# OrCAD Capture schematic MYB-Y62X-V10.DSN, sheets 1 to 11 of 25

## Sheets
1 PAGE16 - CAN: size C; title: MYB-Y62X-V01; rev: V1.0; note: RS485 & MCU_MCAN
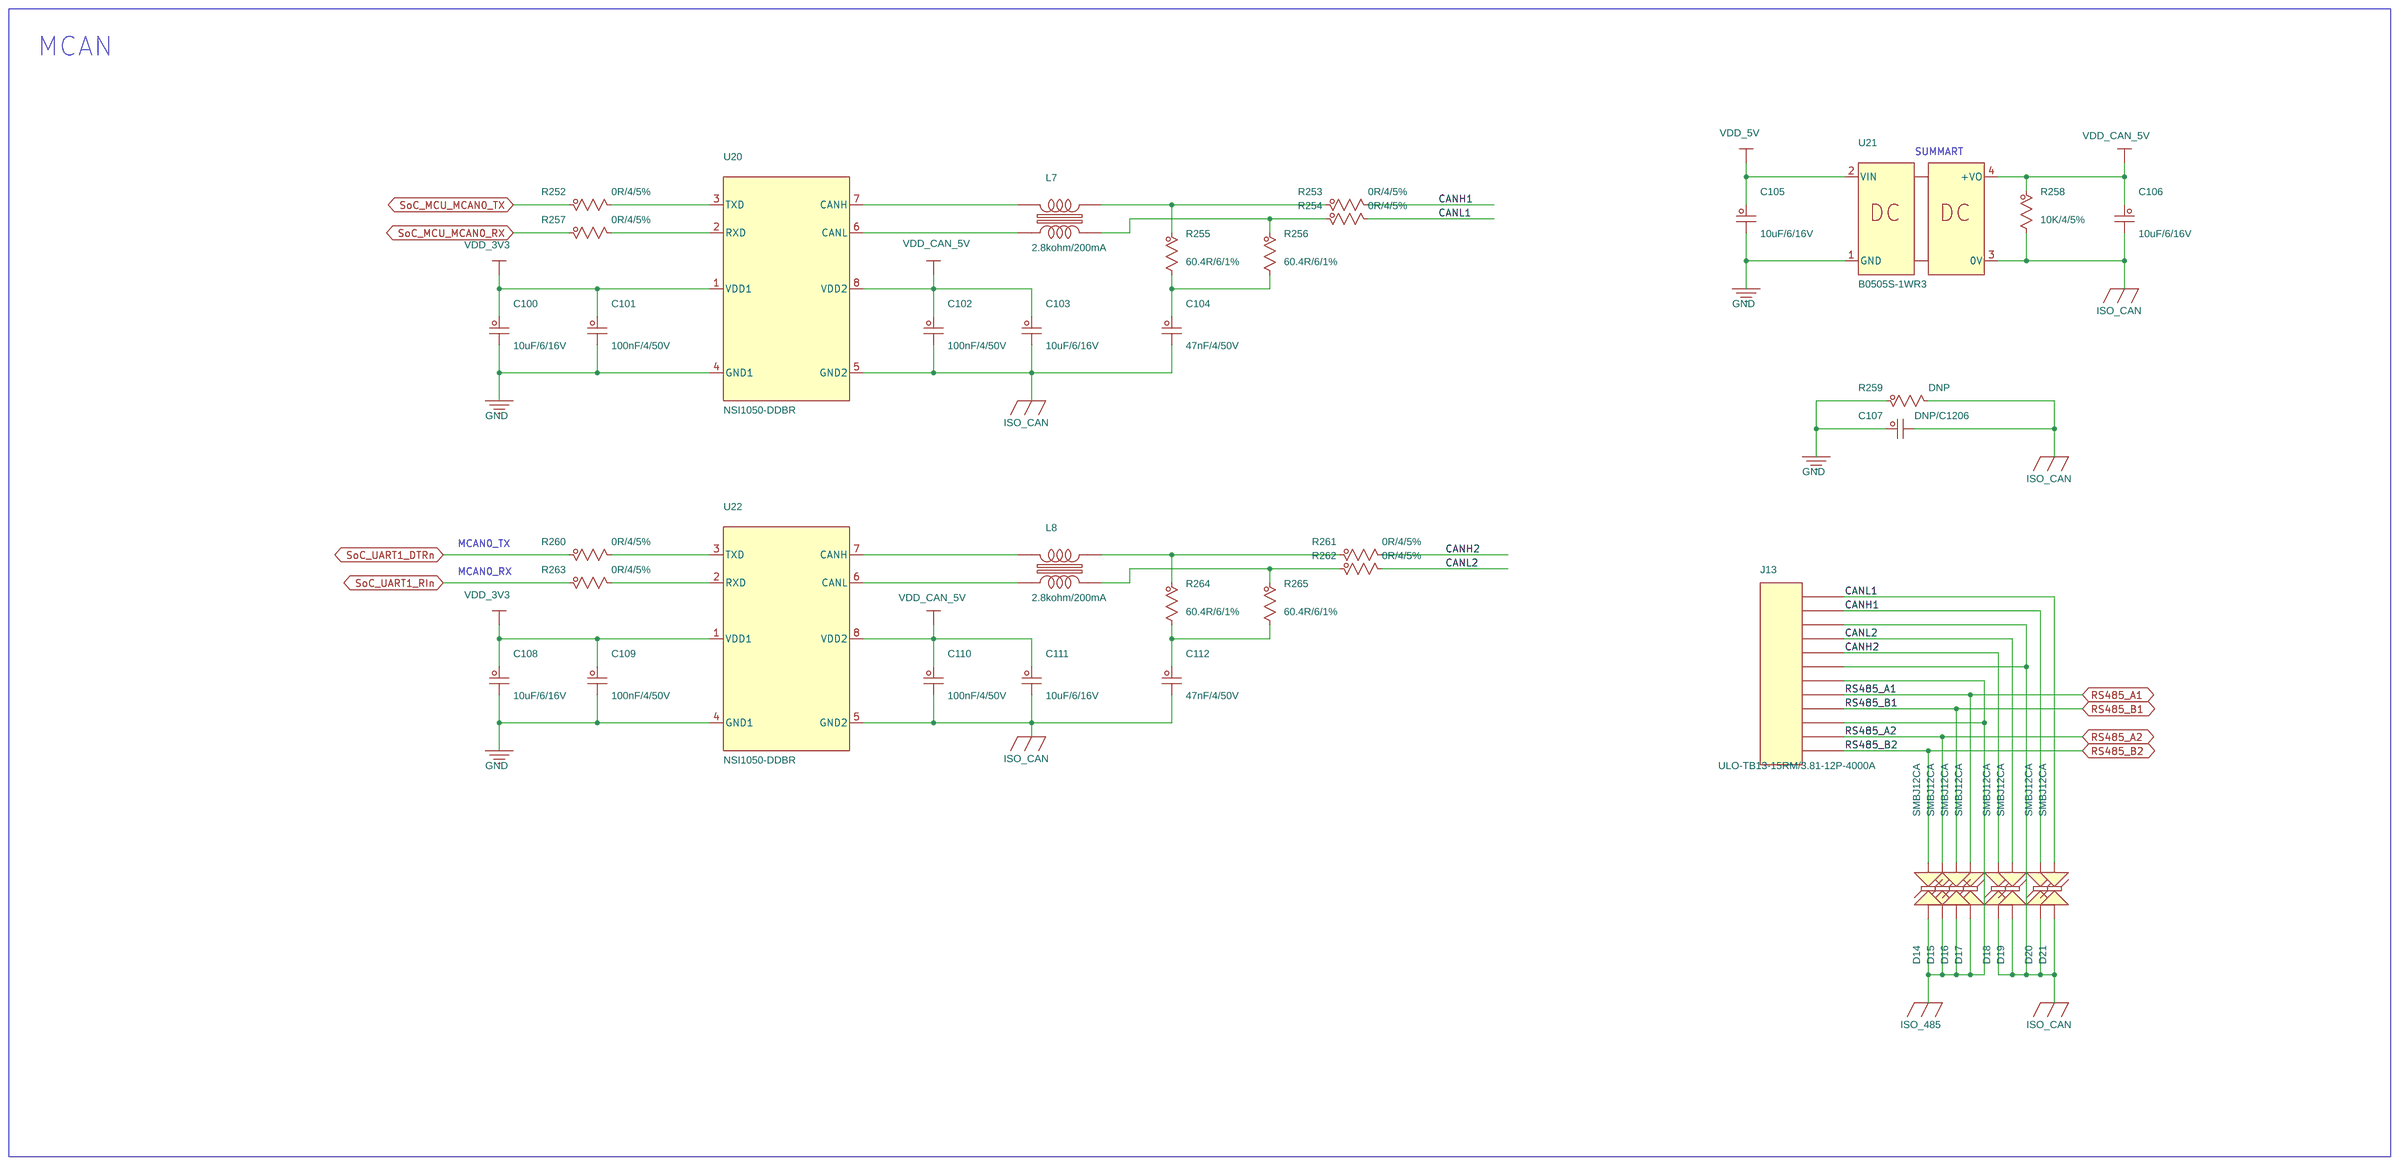
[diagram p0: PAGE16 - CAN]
2 PAGE15 - RS485: size C
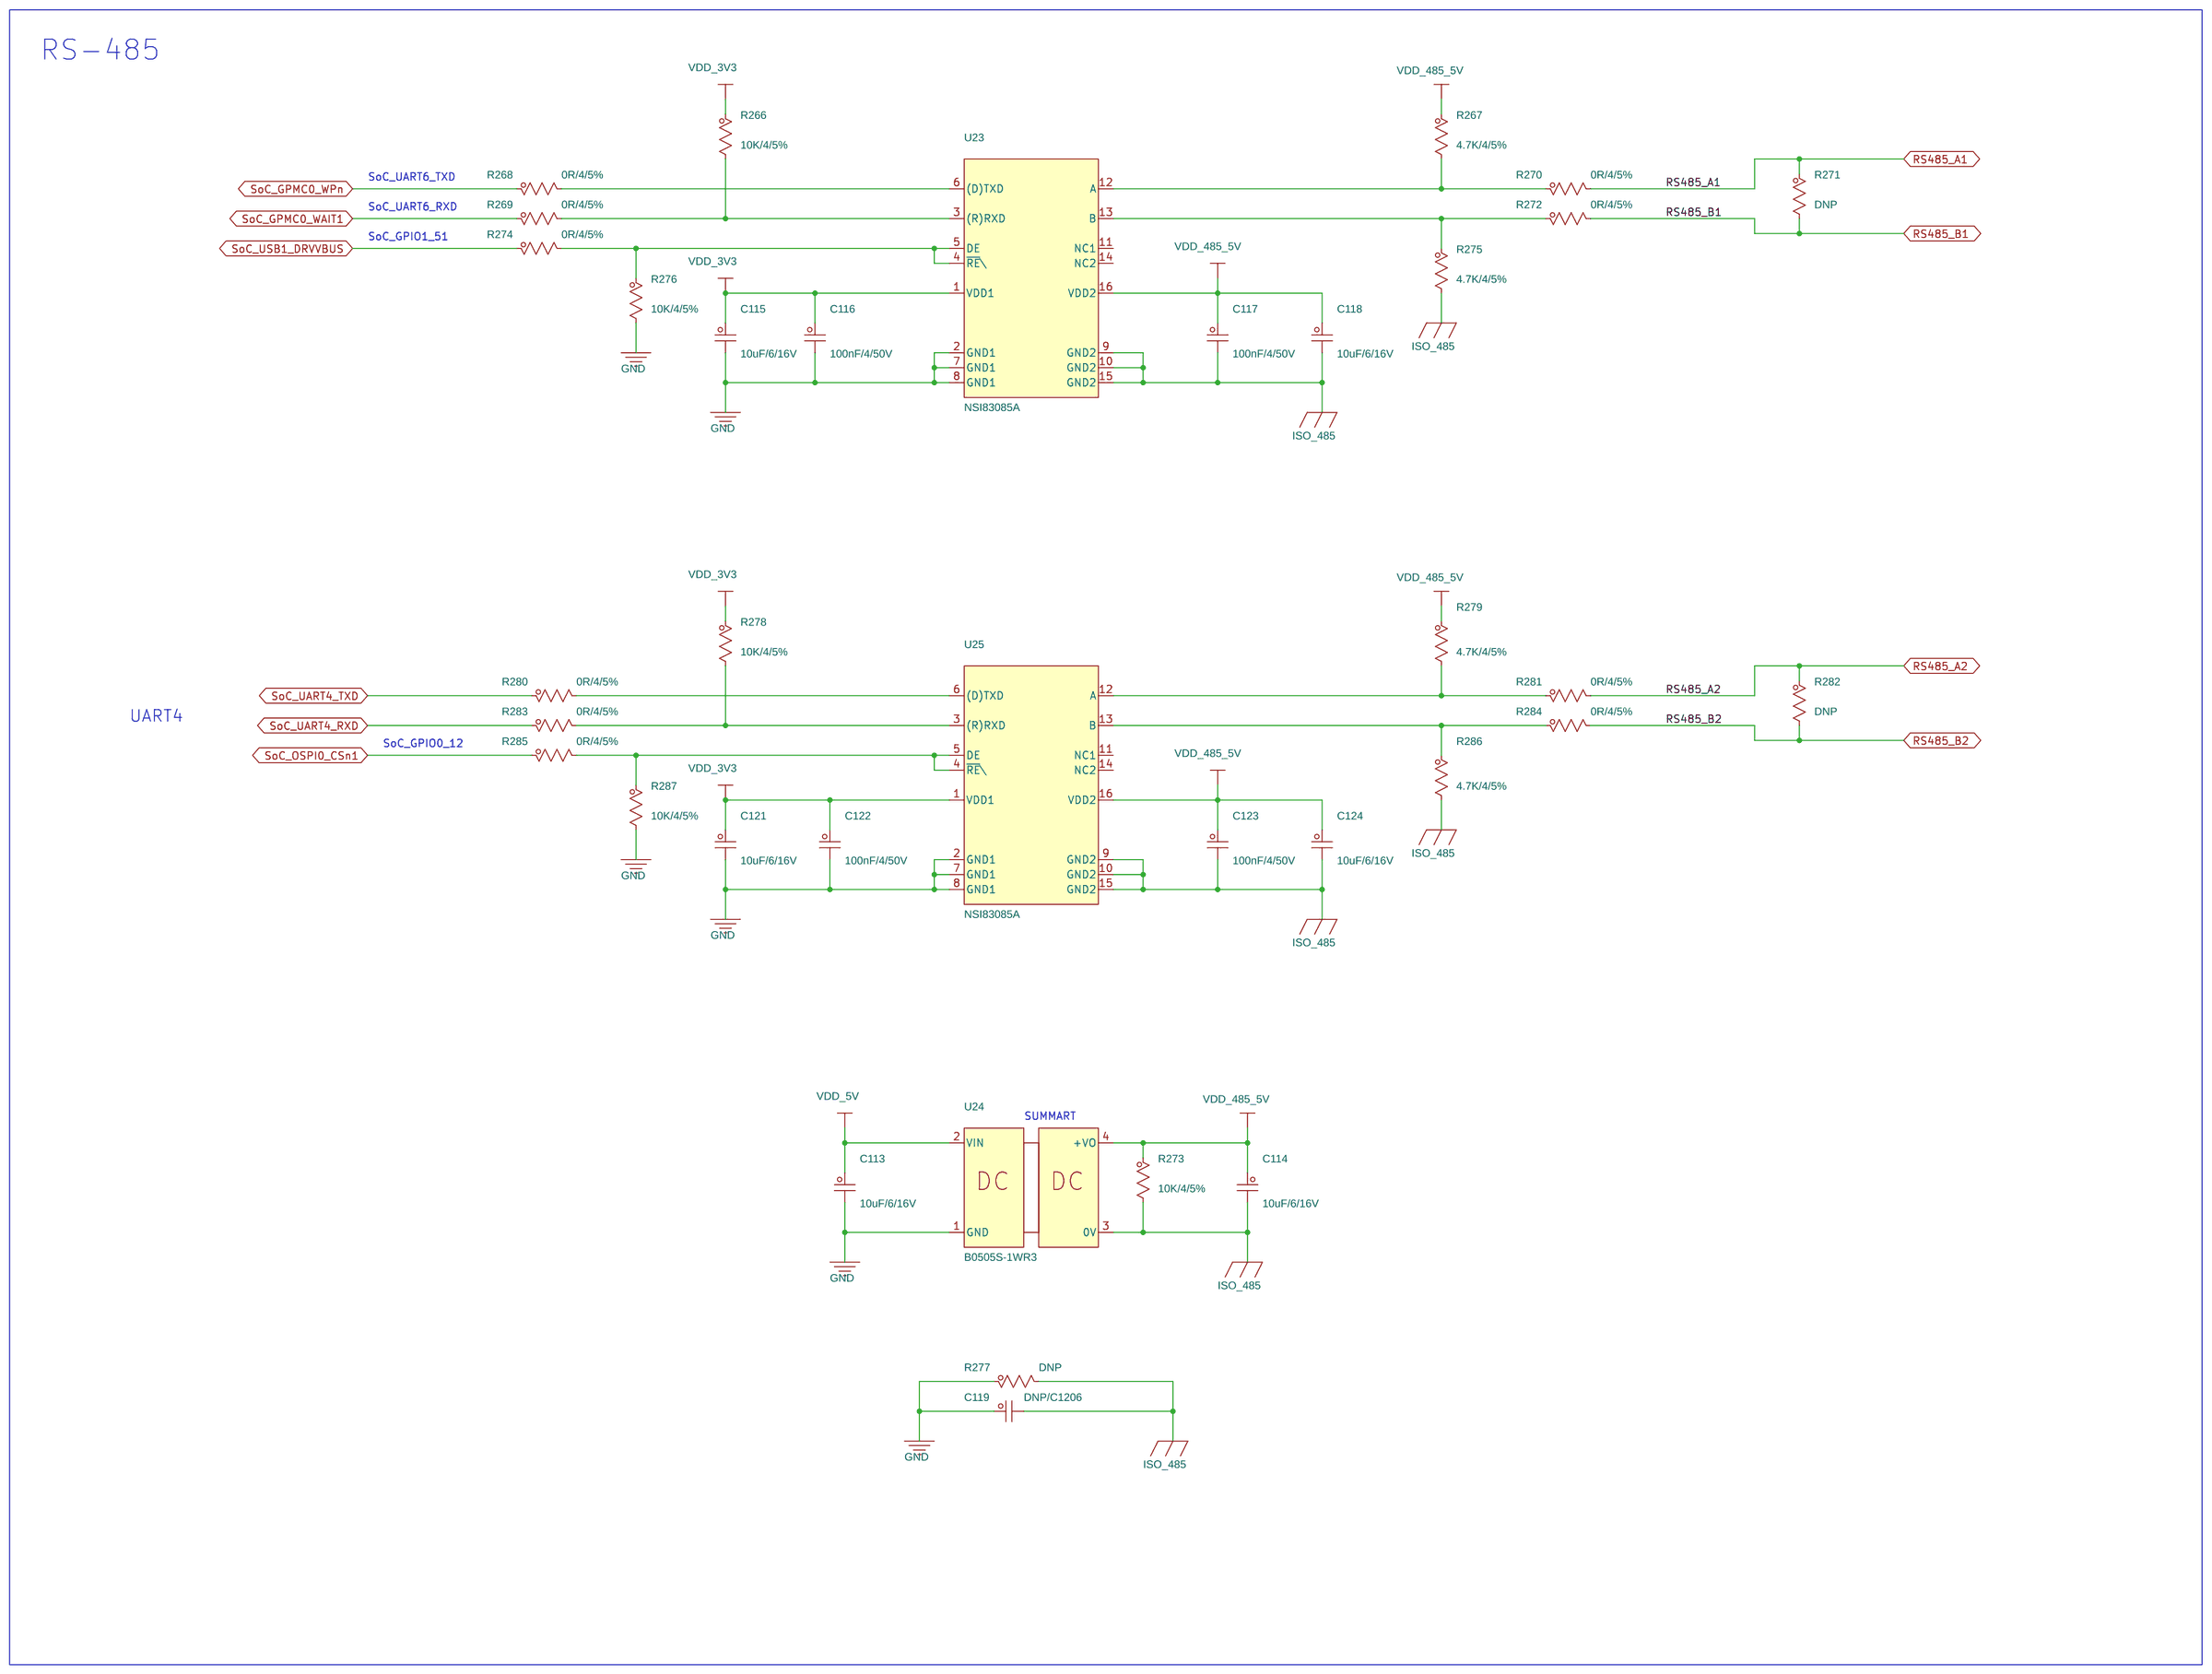
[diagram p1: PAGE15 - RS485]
3 PAGE01- REVISION HISTORY: note: REVISION HISTORY
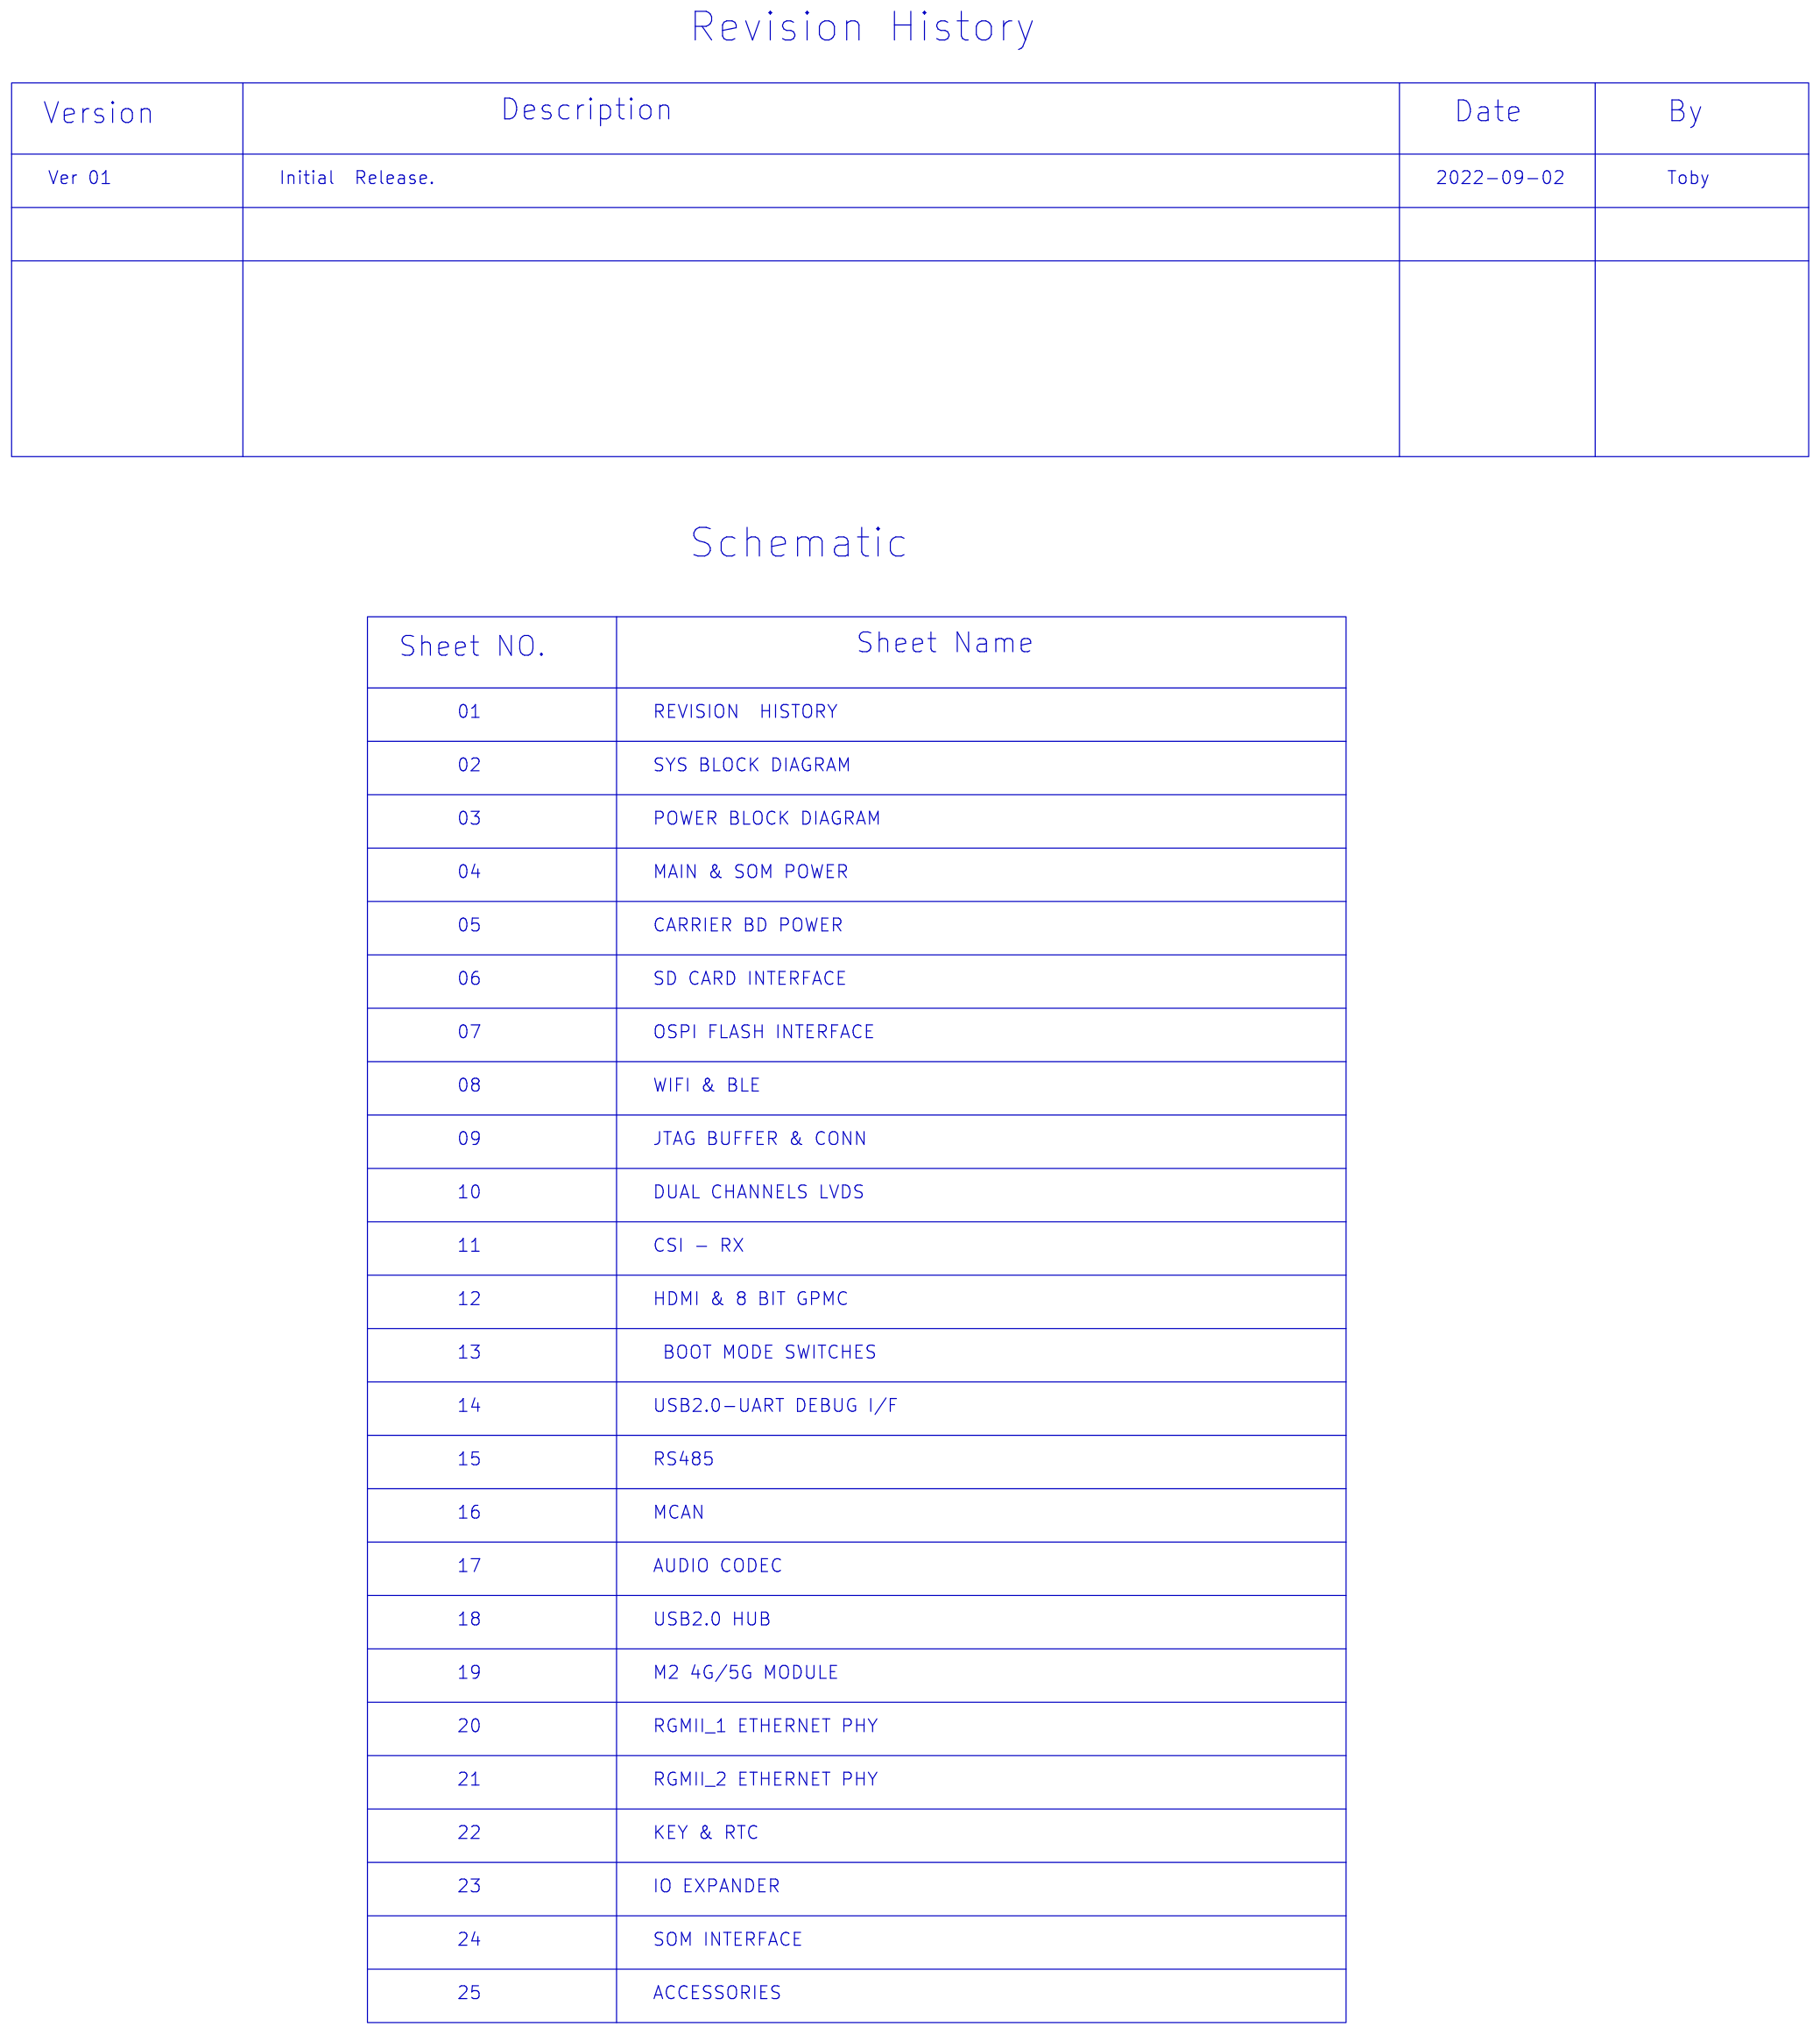
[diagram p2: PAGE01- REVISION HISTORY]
4 PAGE02 - SYS BLOCK DIAGRAM: note: SYS BLOCK DIAGRAM
5 PAGE03 - POWER BLOCK DIAGRAM: note: POWER BLOCK DIAGRAM
6 PAGE04 - MAIN & SOM POWER #: size B; note: MAIN & SOM POWER
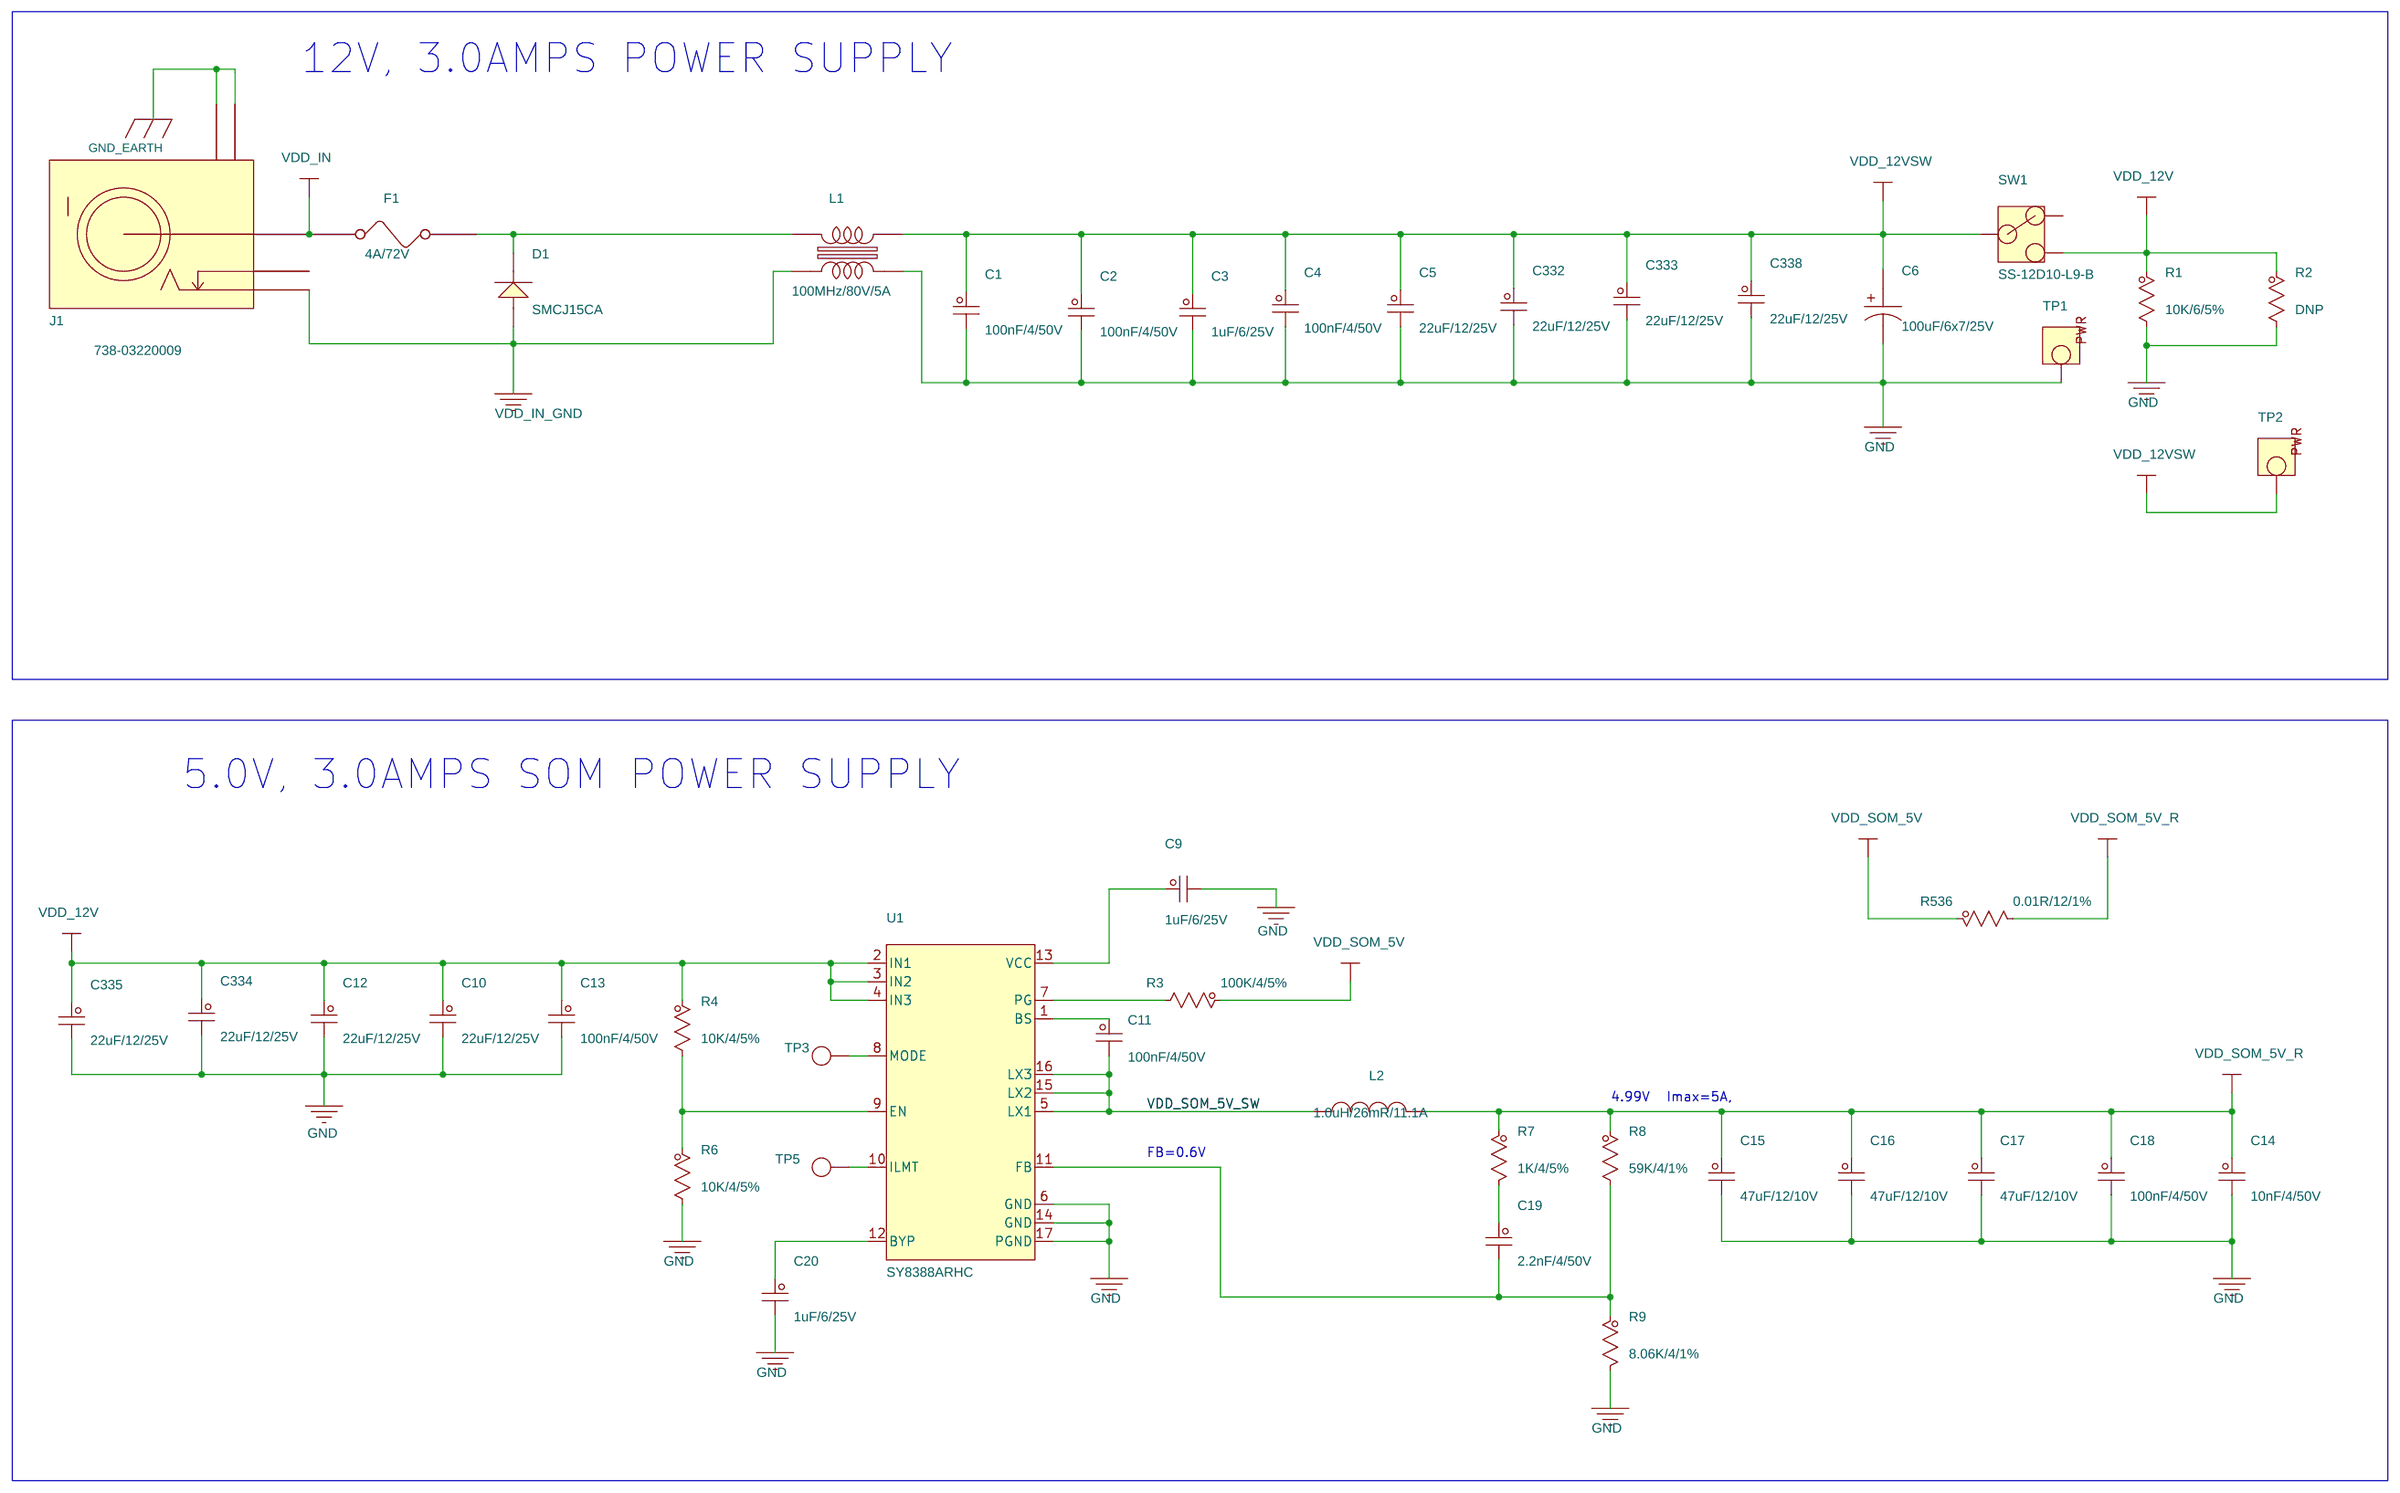
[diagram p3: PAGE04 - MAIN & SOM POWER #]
7 PAGE05 - CARRIER BD POWER #: size A3; note: CARRIER BD POWER
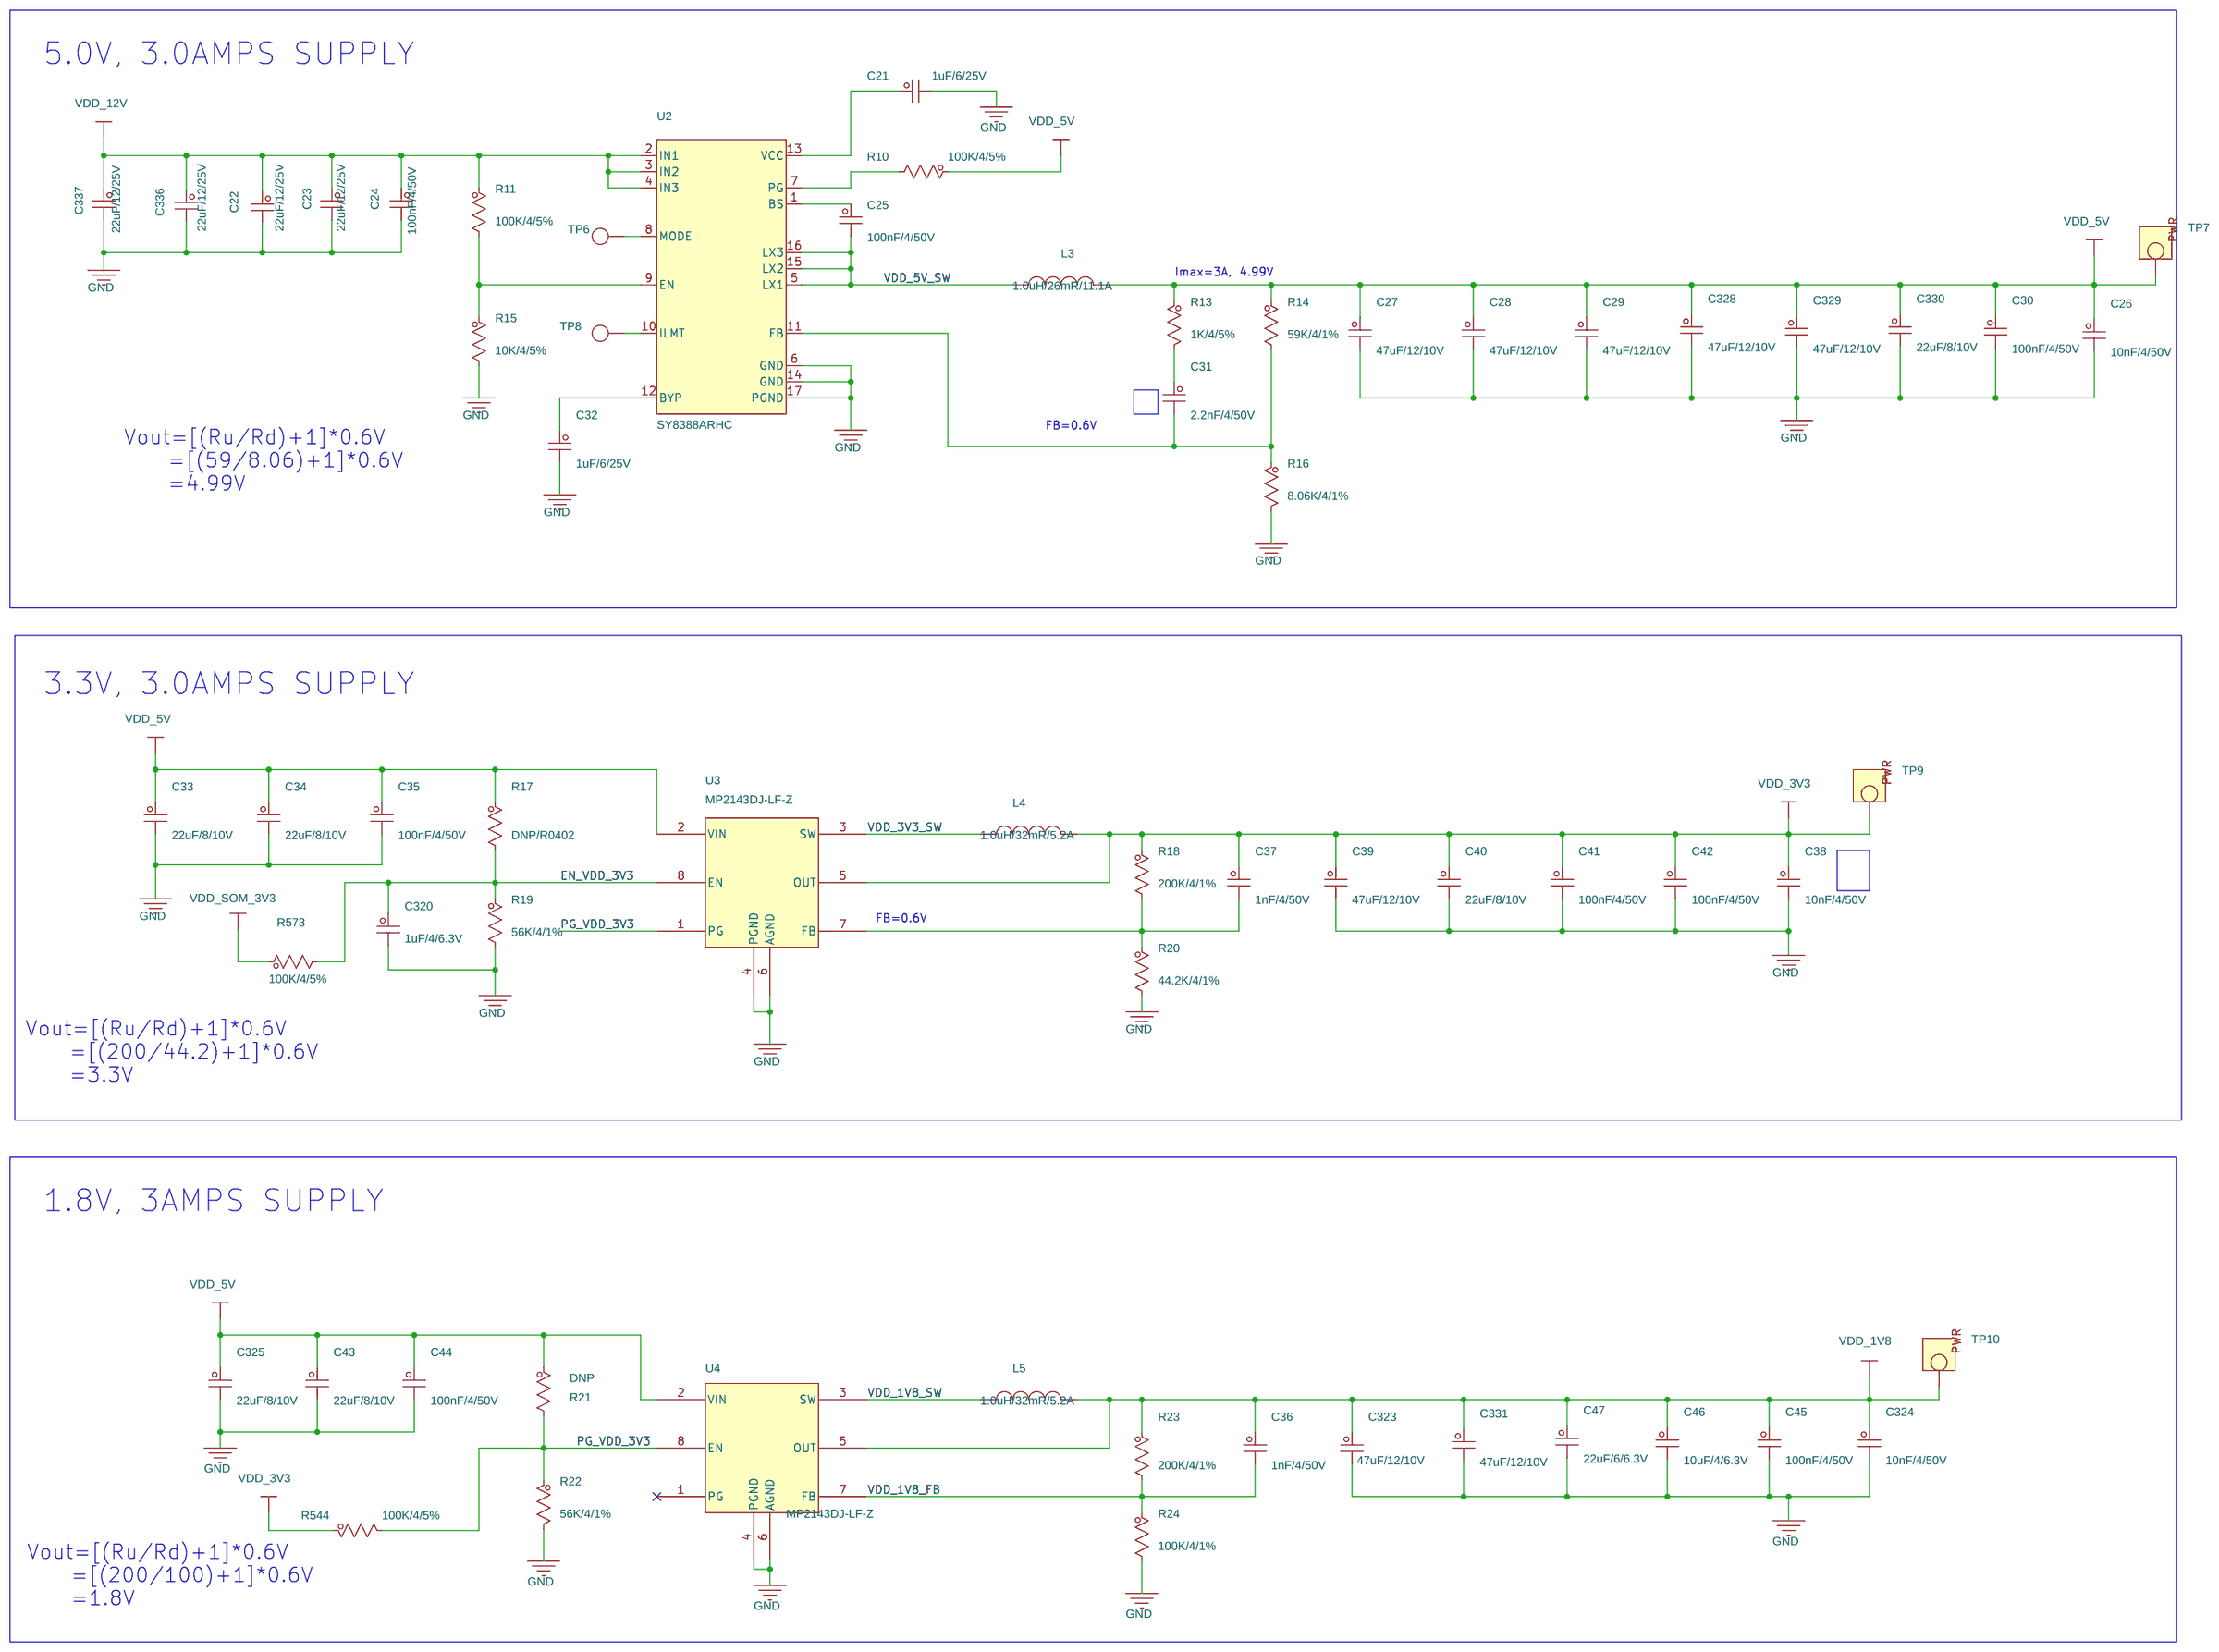
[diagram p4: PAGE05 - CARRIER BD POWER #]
8 PAGE06 - SD CARD INTERFACE #: size B; note: SD CARD INTERFACE
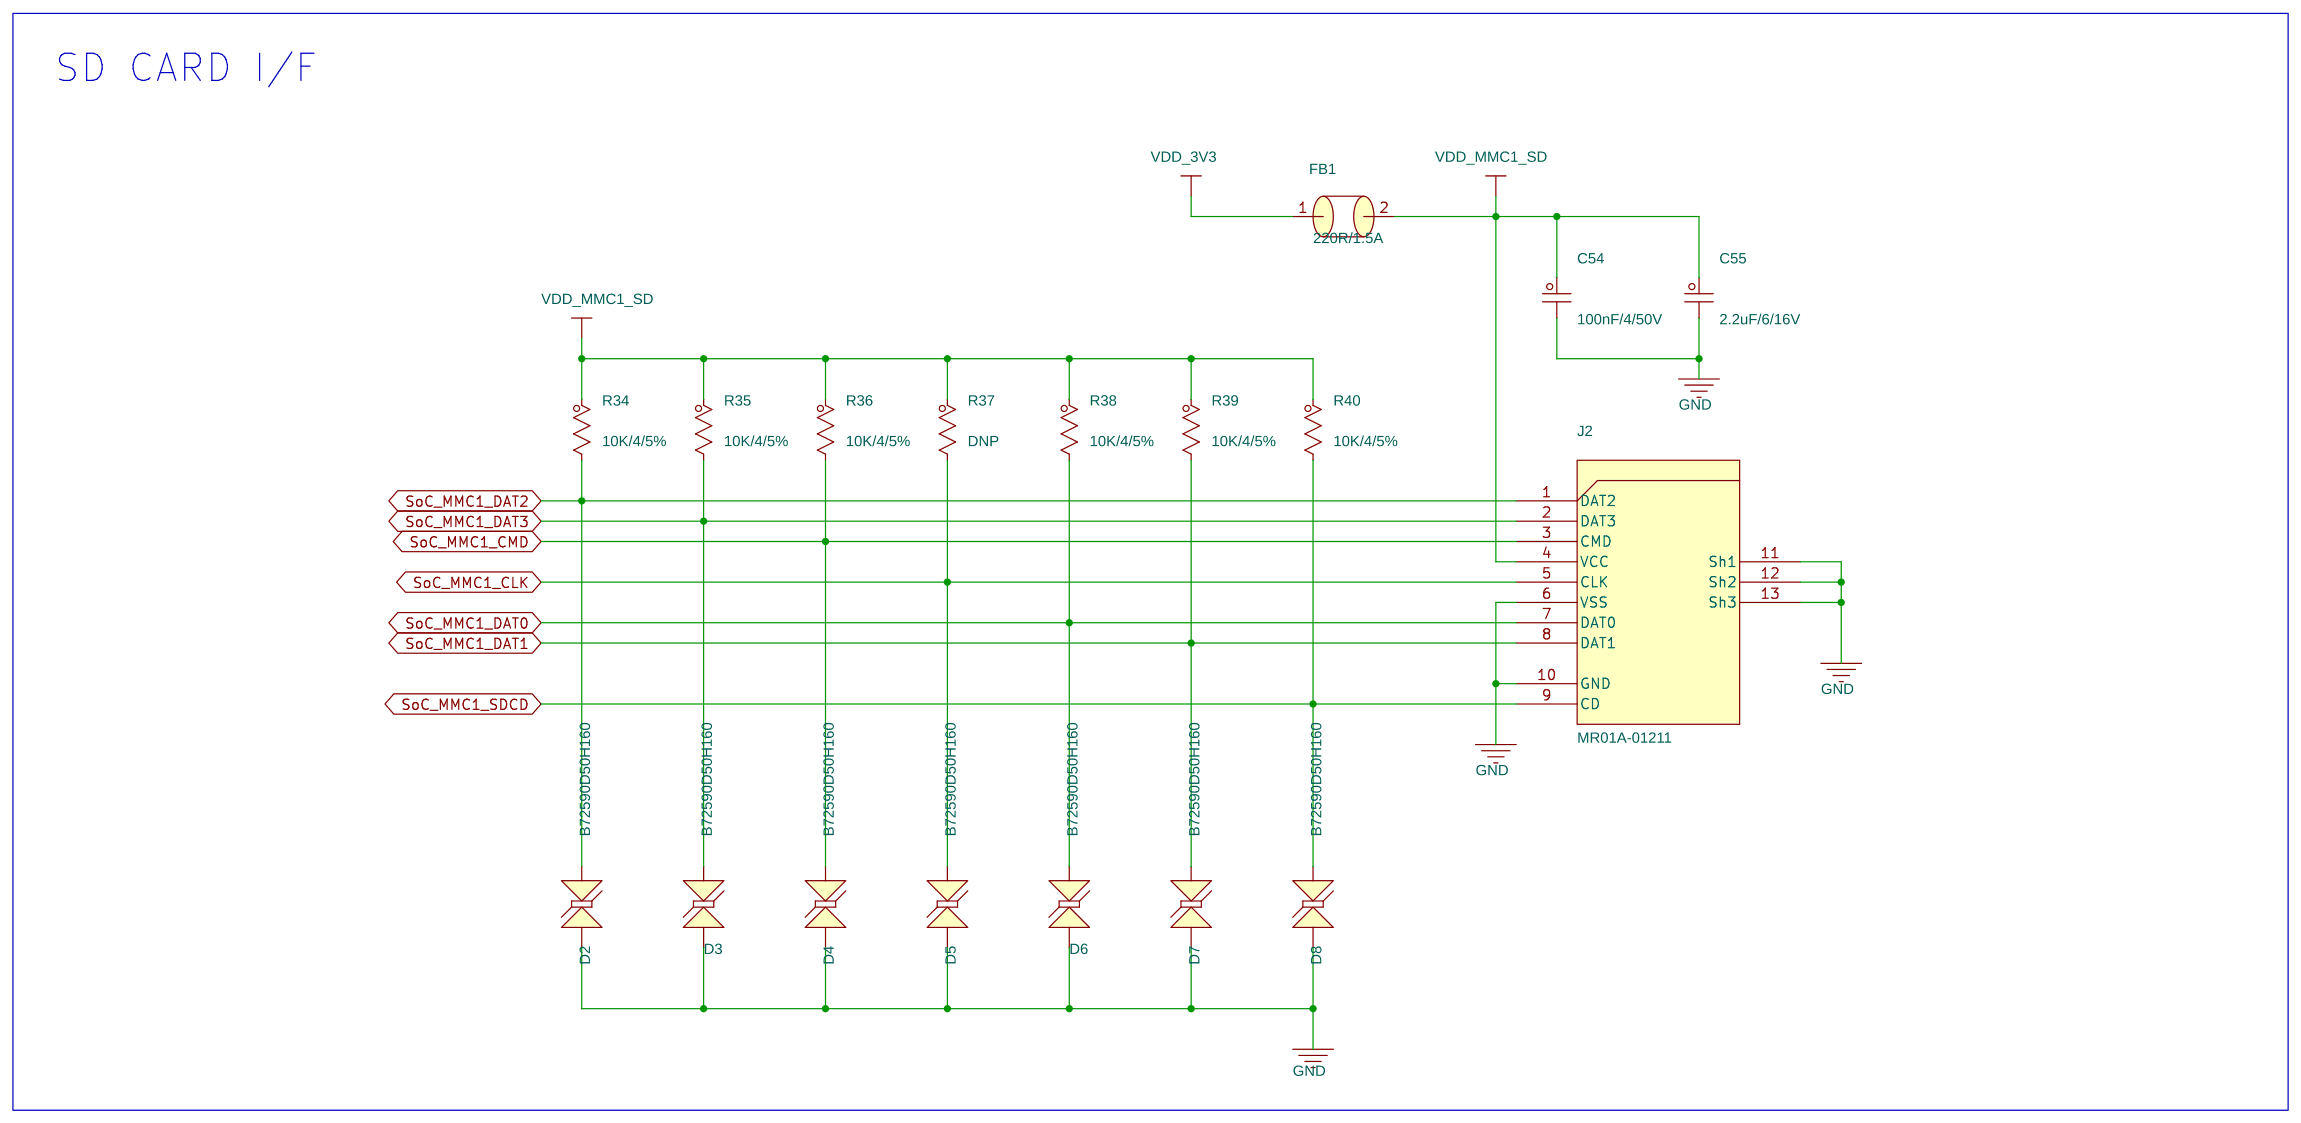
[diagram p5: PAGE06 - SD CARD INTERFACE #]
9 PAGE07 - OSPI FLASH INTERFACE #: size B; note: OSPI INTERFACE
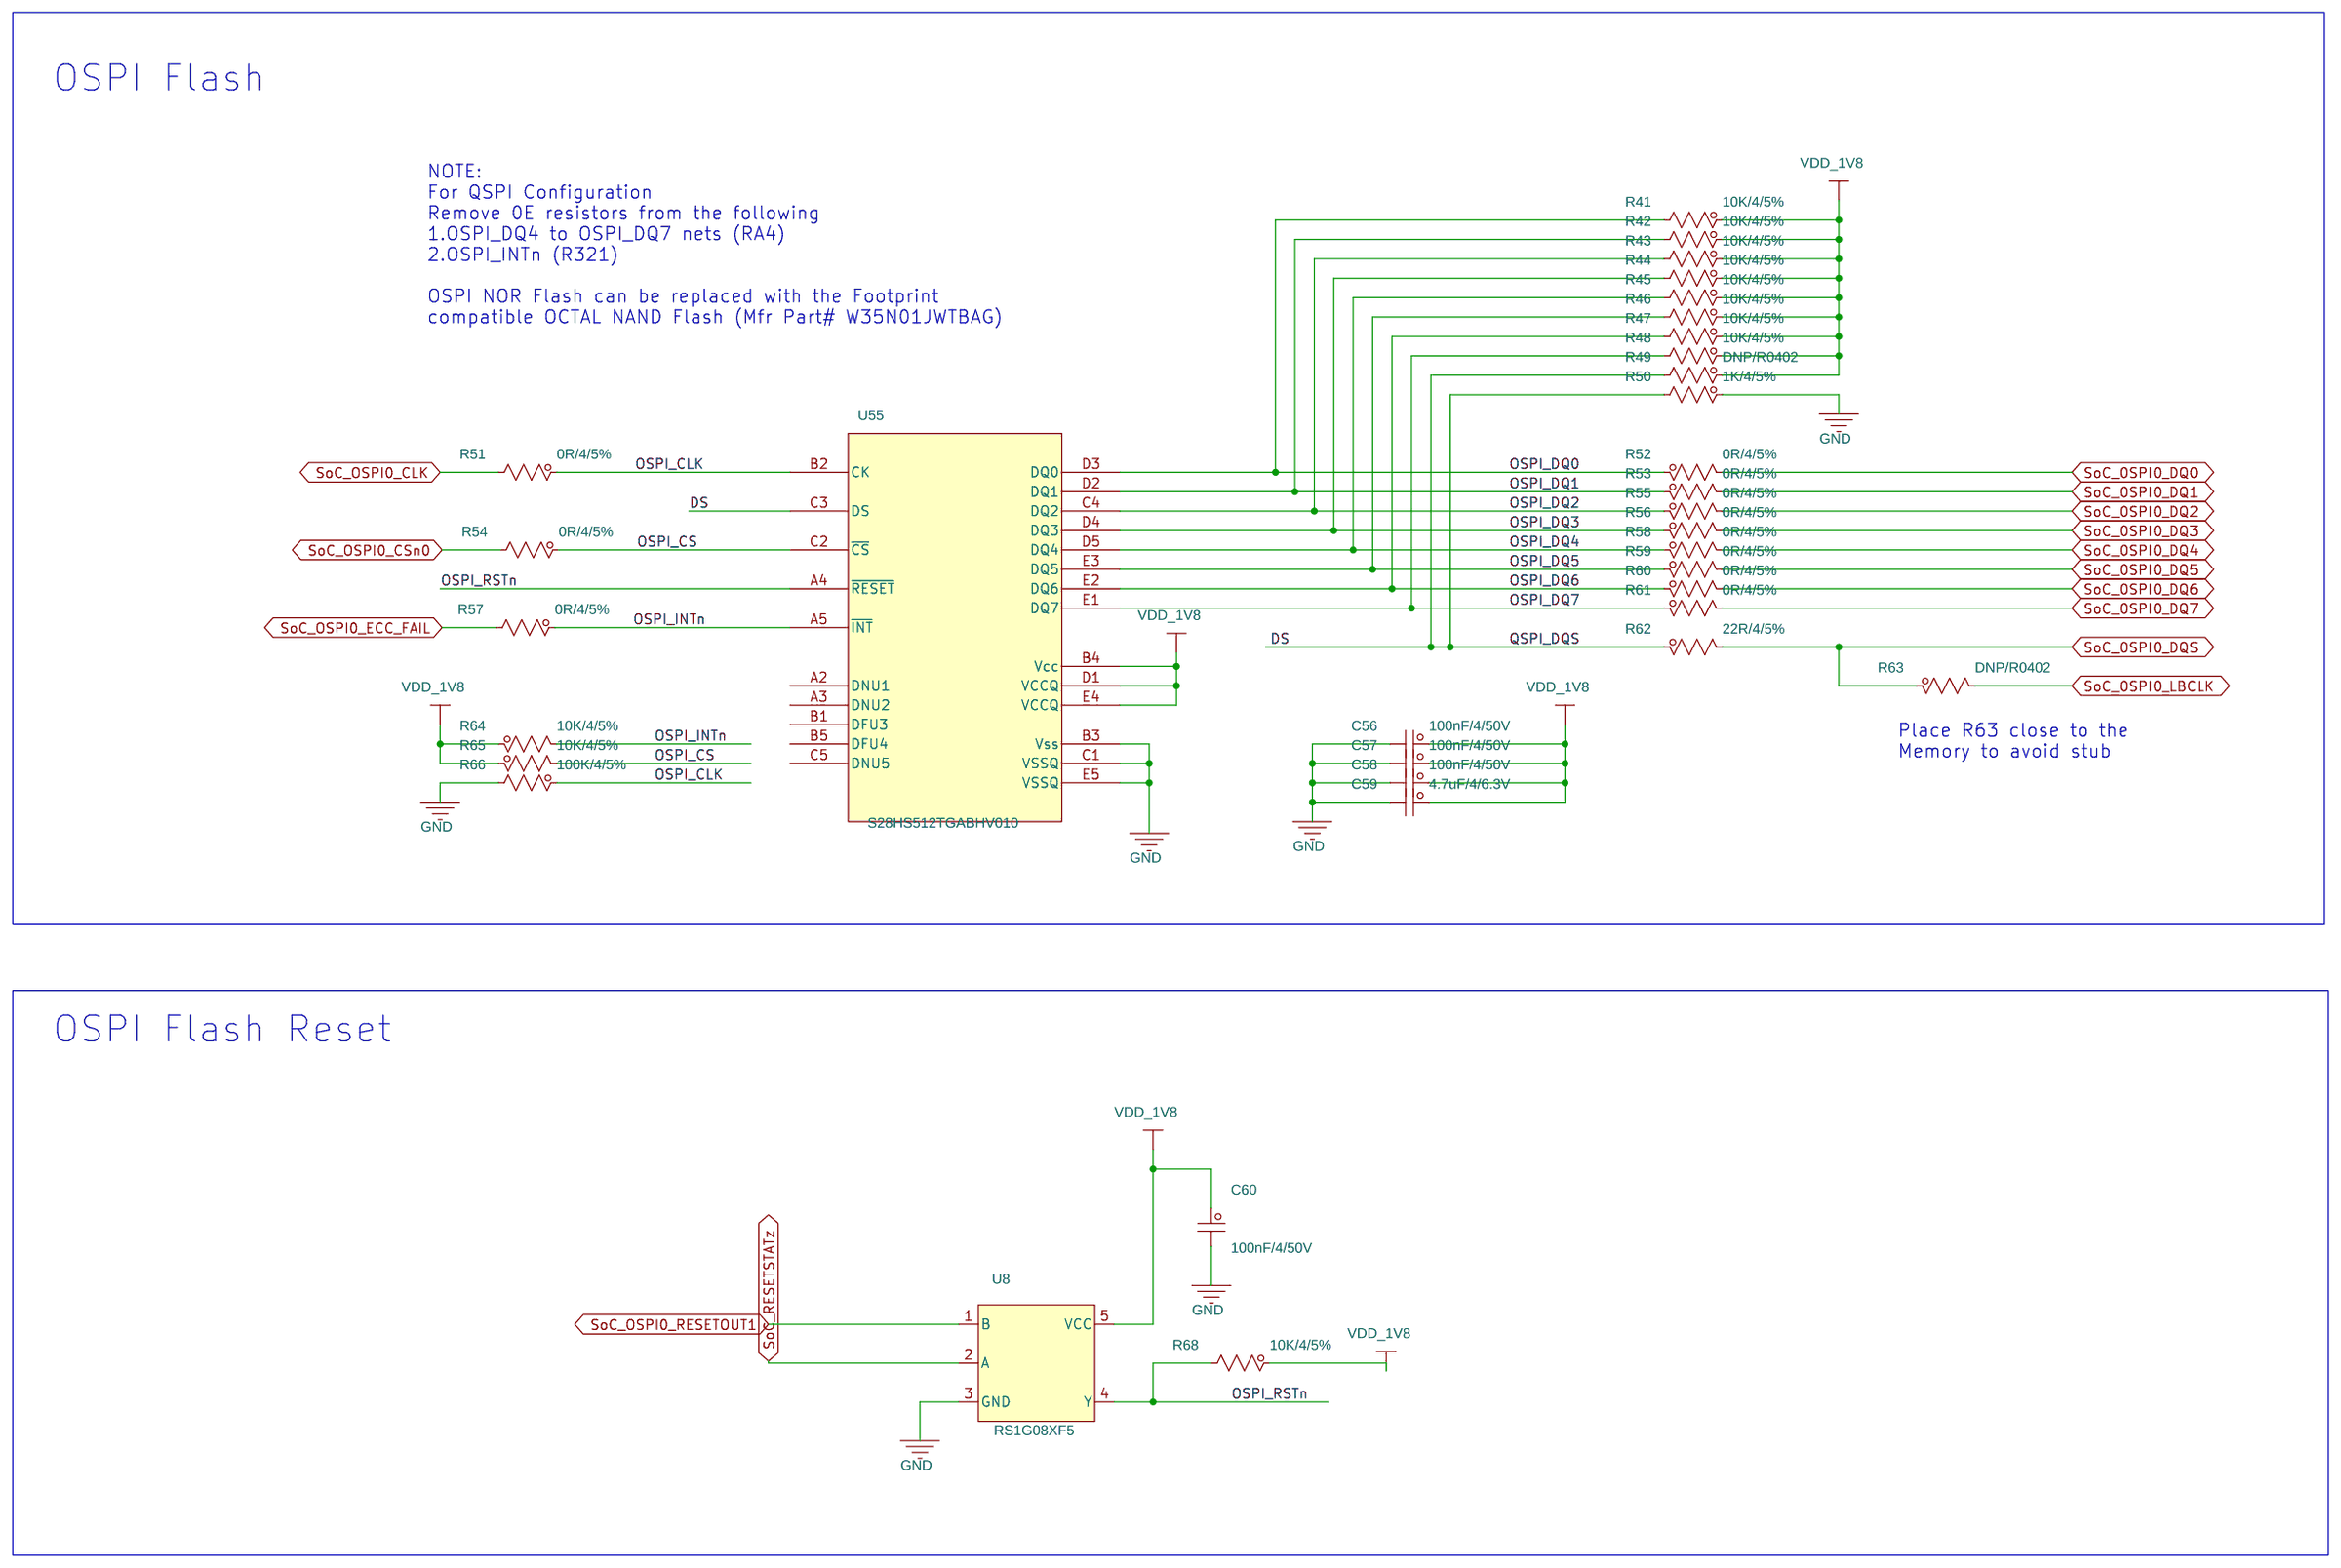
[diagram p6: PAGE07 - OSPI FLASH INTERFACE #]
10 PAGE08 - WIFI & BLE #: size A3; note: WIFI & BLE
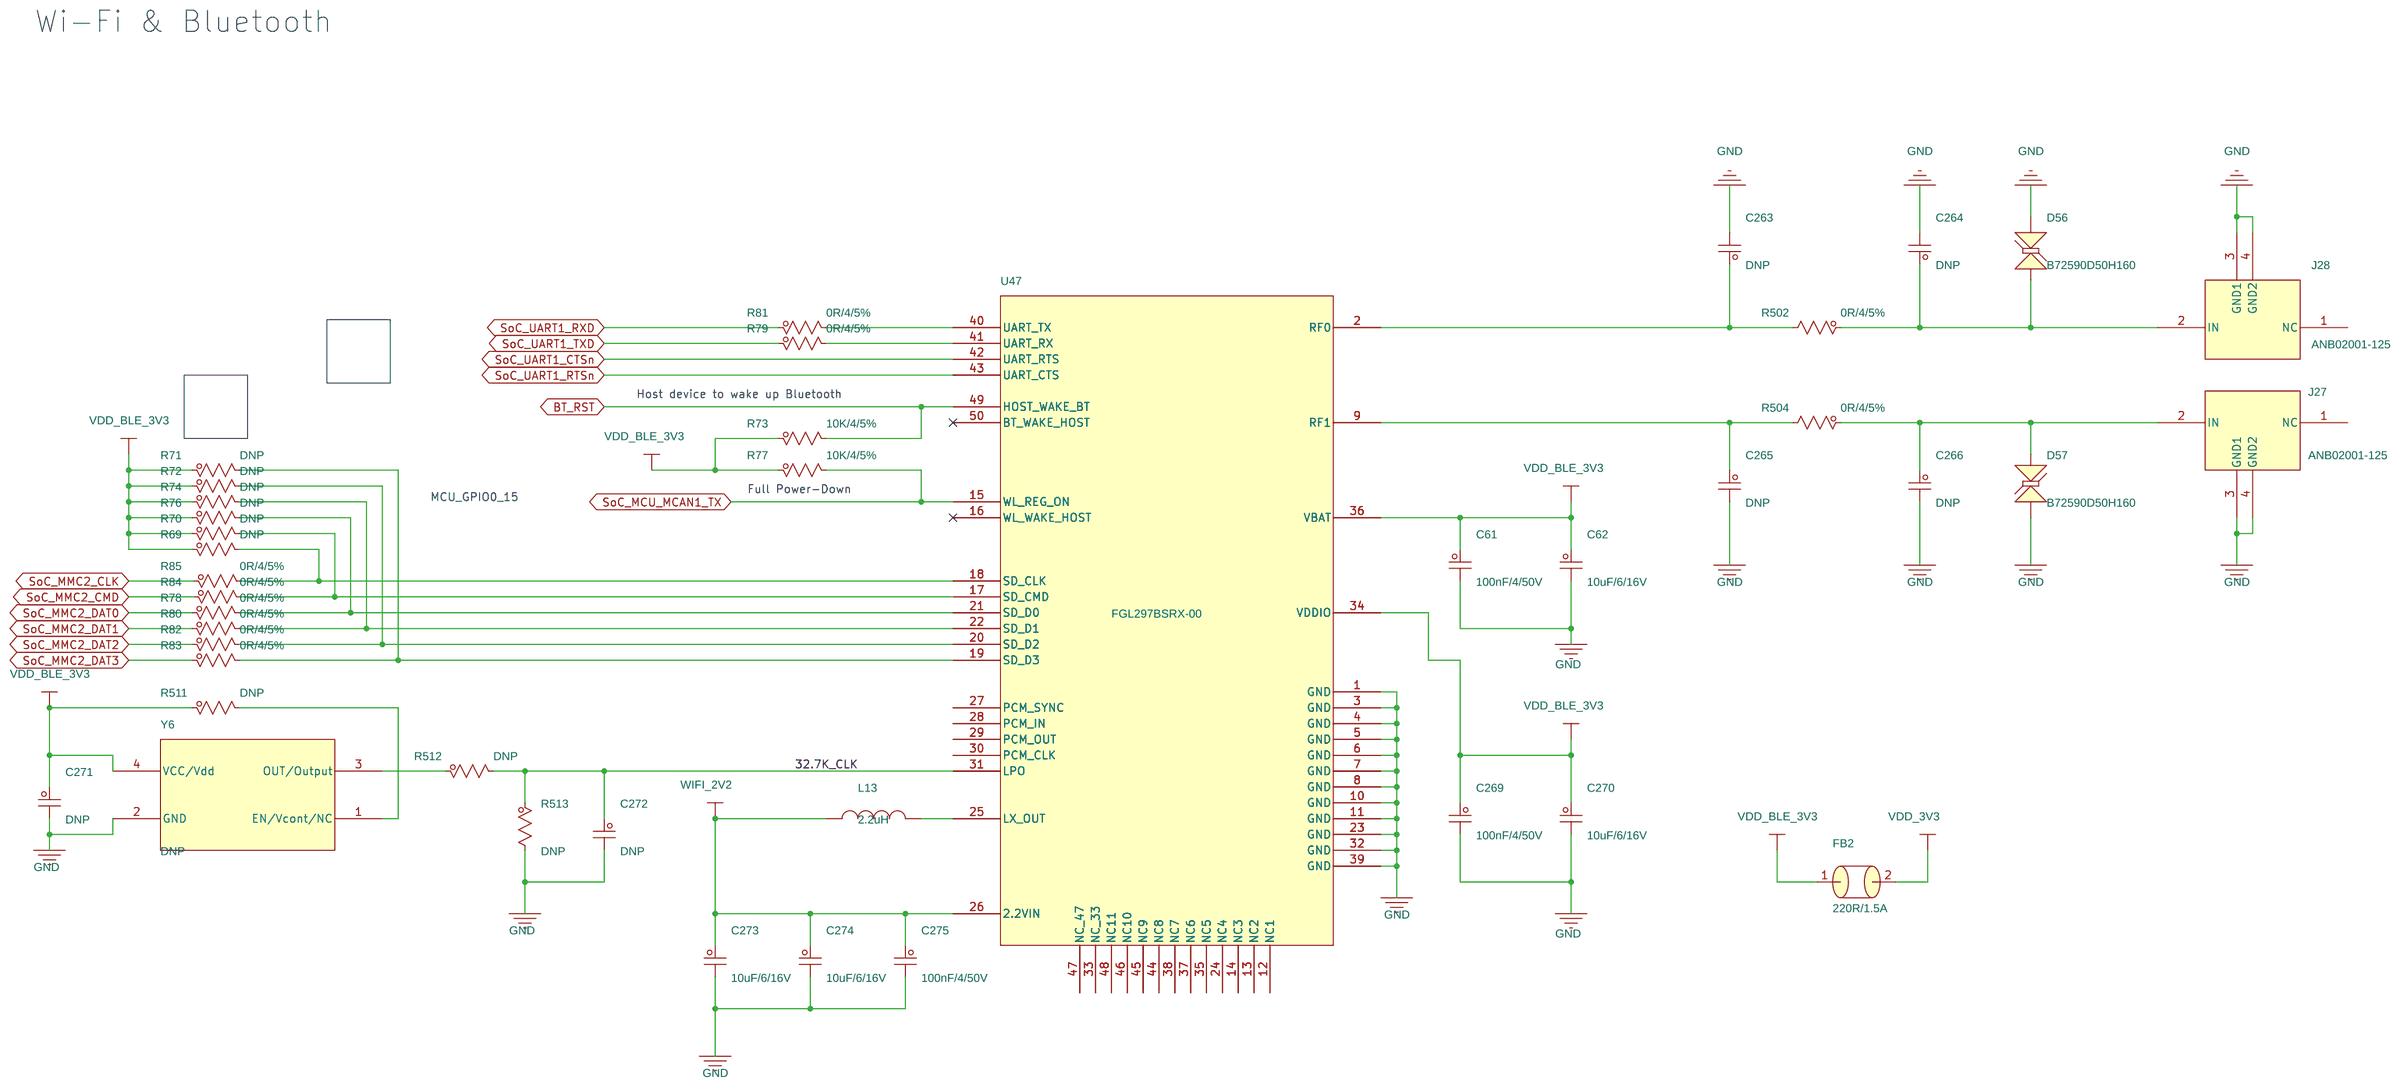
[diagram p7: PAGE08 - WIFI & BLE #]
11 PAGE09 - JTAG CONNECTOR: size B; note: JTAG CONNECTOR
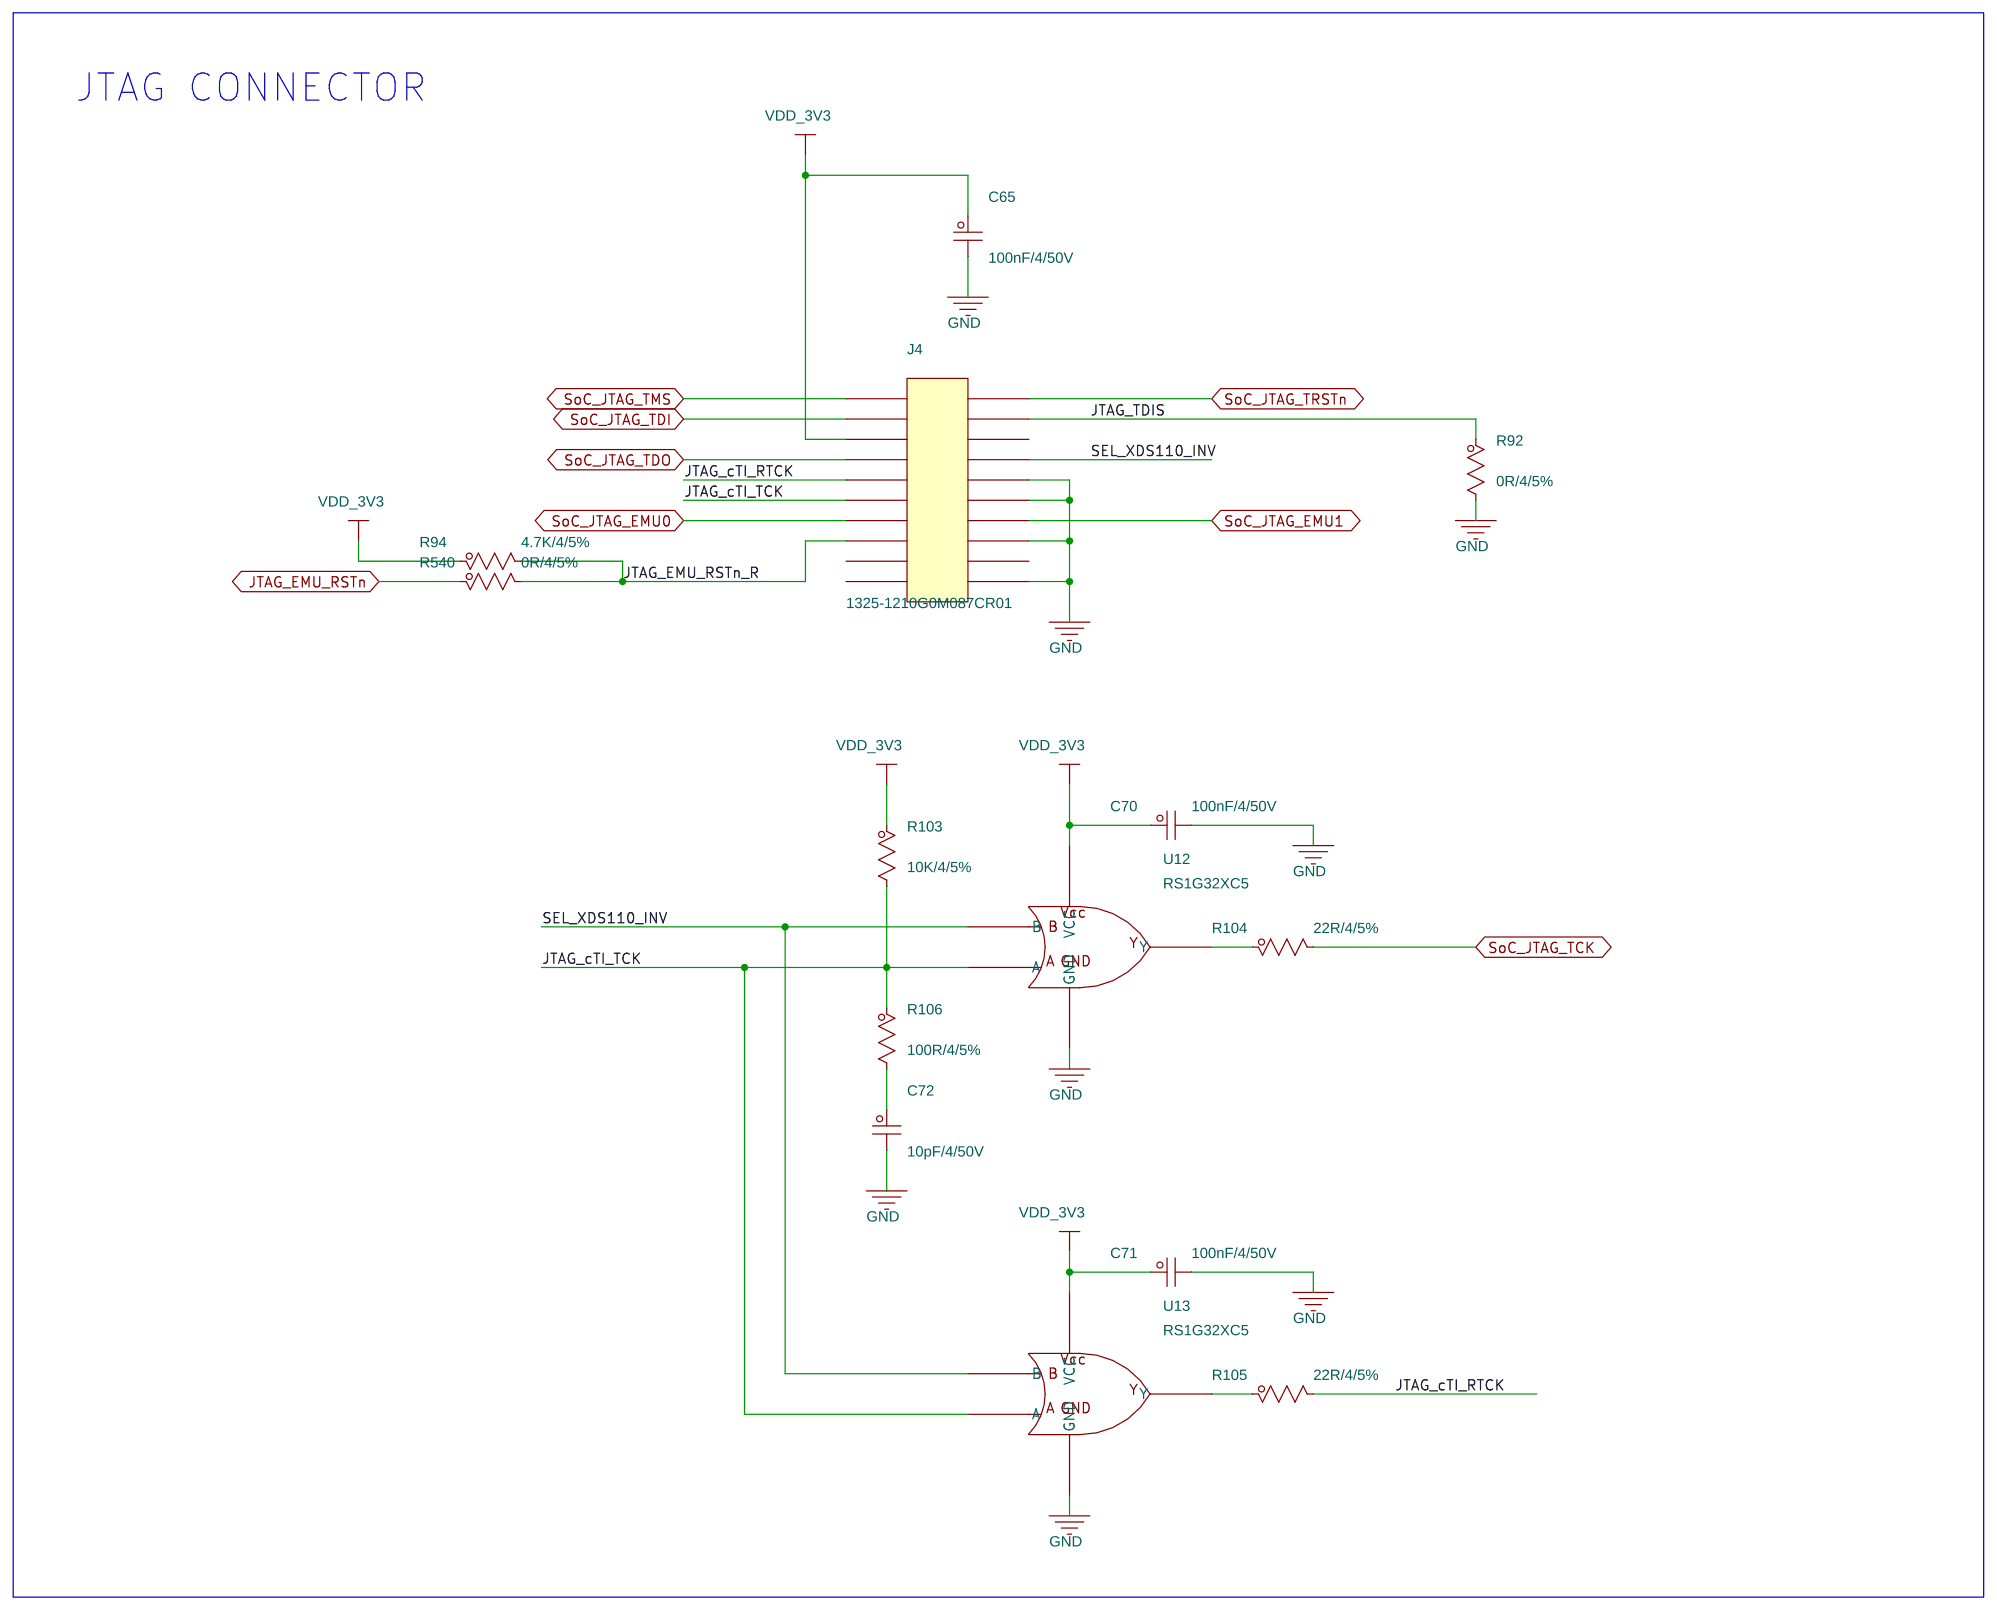
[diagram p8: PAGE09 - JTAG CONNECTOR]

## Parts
sheet PAGE04 - MAIN & SOM POWER #
C1  100nF/4/50V  [C0402]
C2  100nF/4/50V  [C0402]
C3  1uF/6/25V  [C0603]
C4  100nF/4/50V  [C0402]
C5  22uF/12/25V  [C1206]
C6  100uF/6x7/25V  [CE6x6]
C9  1uF/6/25V  [C0603]
C10  22uF/12/25V  [C1206]
C11  100nF/4/50V  [C0402]
C12  22uF/12/25V  [C1206]
C13  100nF/4/50V  [C0402]
C14  10nF/4/50V  [C0402]
C15  47uF/12/10V  [C1206]
C16  47uF/12/10V  [C1206]
C17  47uF/12/10V  [C1206]
C18  100nF/4/50V  [C0402]
C19  2.2nF/4/50V  [C0402]
C20  1uF/6/25V  [C0603]
C332  22uF/12/25V  [C1206]
C333  22uF/12/25V  [C1206]
C334  22uF/12/25V  [C1206]
C335  22uF/12/25V  [C1206]
C338  22uF/12/25V  [C1206]
D1  SMCJ15CA  [DO-214AB]
F1  4A/72V  [F1206]
J1  738-03220009  [738-032XX009]
L1  100MHz/80V/5A  [indcm-acm7060]
L2  1.0uH/26mR/11.1A  [L4_0X4_0]
R1  10K/6/5%  [R0603]
R2  DNP  [R0402]
R3  100K/4/5%  [R0402]
R4  10K/4/5%  [R0402]
R6  10K/4/5%  [R0402]
R7  1K/4/5%  [R0402]
R8  59K/4/1%  [R0402]
R9  8.06K/4/1%  [R0402]
R536  0.01R/12/1%  [R1206]
SW1  SS-12D10-L9-B  [SW-SS-12D10-L9-B]
TP1  SMD  [HOLE-TP0_9S16]
TP2  SMD  [HOLE-TP0_9S16]
TP3  SMD  [test0_8-smd]
TP5  SMD  [test0_8-smd]
U1  SY8388ARHC  [QFN16_0_45]
sheet PAGE05 - CARRIER BD POWER #
C21  1uF/6/25V  [C0603]
C22  22uF/12/25V  [C1206]
C23  22uF/12/25V  [C1206]
C24  100nF/4/50V  [C0402]
C25  100nF/4/50V  [C0402]
C26  10nF/4/50V  [C0402]
C27  47uF/12/10V  [C1206]
C28  47uF/12/10V  [C1206]
C29  47uF/12/10V  [C1206]
C30  100nF/4/50V  [C0402]
C31  2.2nF/4/50V  [C0402]
C32  1uF/6/25V  [C0603]
C33  22uF/8/10V  [C0805]
C34  22uF/8/10V  [C0805]
C35  100nF/4/50V  [C0402]
C36  1nF/4/50V  [C0402]
C37  1nF/4/50V  [C0402]
C38  10nF/4/50V  [C0402]
C39  47uF/12/10V  [C1206]
C40  22uF/8/10V  [C0805]
C41  100nF/4/50V  [C0402]
C42  100nF/4/50V  [C0402]
C43  22uF/8/10V  [C0805]
C44  100nF/4/50V  [C0402]
C45  100nF/4/50V  [C0402]
C46  10uF/4/6.3V  [C0402]
C47  22uF/6/6.3V  [C0603]
C320  1uF/4/6.3V  [C0402]
C323  47uF/12/10V  [C1206]
C324  10nF/4/50V  [C0402]
C325  22uF/8/10V  [C0805]
C328  47uF/12/10V  [C1206]
C329  47uF/12/10V  [C1206]
C330  22uF/8/10V  [C0805]
C331  47uF/12/10V  [C1206]
C336  22uF/12/25V  [C1206]
C337  22uF/12/25V  [C1206]
L3  1.0uH/26mR/11.1A  [L4_0X4_0]
L4  1.0uH/32mR/5.2A  [l2x2_5]
L5  1.0uH/32mR/5.2A  [l2x2_5]
R10  100K/4/5%  [R0402]
R11  100K/4/5%  [R0402]
R13  1K/4/5%  [R0402]
R14  59K/4/1%  [R0402]
R15  10K/4/5%  [R0402]
R16  8.06K/4/1%  [R0402]
R17  DNP/R0402  [R0402]
R18  200K/4/1%  [R0402]
R19  56K/4/1%  [R0402]
R20  44.2K/4/1%  [R0402]
R21  DNP  [R0402]
R22  56K/4/1%  [R0402]
R23  200K/4/1%  [R0402]
R24  100K/4/1%  [R0402]
R544  100K/4/5%  [R0402]
R573  100K/4/5%  [R0402]
TP6  SMD  [test0_8-smd]
TP7  SMD  [HOLE-TP0_9S16]
TP8  SMD  [test0_8-smd]
TP9  SMD  [HOLE-TP0_9S16]
TP10  SMD  [HOLE-TP0_9S16]
U2  SY8388ARHC  [QFN16_0_45]
U3  MP2143DJ-LF-Z  [tsot23-8]
U4  MP2143DJ-LF-Z  [tsot23-8]
sheet PAGE06 - SD CARD INTERFACE #
C54  100nF/4/50V  [C0402]
C55  2.2uF/6/16V  [C0603]
D2  B72590D50H160  [D0402]
D3  B72590D50H160  [D0402]
D4  B72590D50H160  [D0402]
D5  B72590D50H160  [D0402]
D6  B72590D50H160  [D0402]
D7  B72590D50H160  [D0402]
D8  B72590D50H160  [D0402]
FB1  220R/1.5A  [FB0603]
J2  MR01A-01211  [SD-MR01A-01211]
R34  10K/4/5%  [R0402]
R35  10K/4/5%  [R0402]
R36  10K/4/5%  [R0402]
R37  DNP  [R0402]
R38  10K/4/5%  [R0402]
R39  10K/4/5%  [R0402]
R40  10K/4/5%  [R0402]
sheet PAGE07 - OSPI FLASH INTERFACE #
C56  100nF/4/50V  [C0402]
C57  100nF/4/50V  [C0402]
C58  100nF/4/50V  [C0402]
C59  4.7uF/4/6.3V  [C0402]
C60  100nF/4/50V  [C0402]
R41  10K/4/5%  [R0402]
R42  10K/4/5%  [R0402]
R43  10K/4/5%  [R0402]
R44  10K/4/5%  [R0402]
R45  10K/4/5%  [R0402]
R46  10K/4/5%  [R0402]
R47  10K/4/5%  [R0402]
R48  10K/4/5%  [R0402]
R49  DNP/R0402  [R0402]
R50  1K/4/5%  [R0402]
R51  0R/4/5%  [R0402]
R52  0R/4/5%  [R0402]
R53  0R/4/5%  [R0402]
R54  0R/4/5%  [R0402]
R55  0R/4/5%  [R0402]
R56  0R/4/5%  [R0402]
R57  0R/4/5%  [R0402]
R58  0R/4/5%  [R0402]
R59  0R/4/5%  [R0402]
R60  0R/4/5%  [R0402]
R61  0R/4/5%  [R0402]
R62  22R/4/5%  [R0402]
R63  DNP/R0402  [R0402]
R64  10K/4/5%  [R0402]
R65  10K/4/5%  [R0402]
R66  100K/4/5%  [R0402]
R68  10K/4/5%  [R0402]
U8  RS1G08XF5  [SOT23-5]
U55  S28HS512TGABHV010  [BGA24]
sheet PAGE08 - WIFI & BLE #
C61  100nF/4/50V  [C0402]
C62  10uF/6/16V  [C0603]
C263  DNP  [C0402]
C264  DNP  [C0402]
C265  DNP  [C0402]
C266  DNP  [C0402]
C269  100nF/4/50V  [C0402]
C270  10uF/6/16V  [C0603]
C271  DNP  [C0402]
C272  DNP  [C0402]
C273  10uF/6/16V  [C0603]
C274  10uF/6/16V  [C0603]
C275  100nF/4/50V  [C0402]
D56  B72590D50H160  [D0402]
D57  B72590D50H160  [D0402]
FB2  220R/1.5A  [FB0603]
J27  ANB02001-125  [ANT-1566230-1]
J28  ANB02001-125  [ANT-1566230-1]
L13  2.2uH  [L3X3]
R69  DNP  [R0402]
R70  DNP  [R0402]
R71  DNP  [R0402]
R72  DNP  [R0402]
R73  10K/4/5%  [R0402]
R74  DNP  [R0402]
R76  DNP  [R0402]
R77  10K/4/5%  [R0402]
R78  0R/4/5%  [R0402]
R79  0R/4/5%  [R0402]
R80  0R/4/5%  [R0402]
R81  0R/4/5%  [R0402]
R82  0R/4/5%  [R0402]
R83  0R/4/5%  [R0402]
R84  0R/4/5%  [R0402]
R85  0R/4/5%  [R0402]
R502  0R/4/5%  [R0402]
R504  0R/4/5%  [R0402]
R511  DNP  [R0402]
R512  DNP  [R0402]
R513  DNP  [R0402]
U47  FGL297BSRX-00  [MODULE-L297B-SR]
Y6  DNP  [3225]
sheet PAGE09 - JTAG CONNECTOR
C65  100nF/4/50V  [C0402]
C70  100nF/4/50V  [C0402]
C71  100nF/4/50V  [C0402]
C72  10pF/4/50V  [C0402]
J4  1325-1210G0M087CR01  [CONN2x10-1_27]
R92  0R/4/5%  [R0402]
R94  4.7K/4/5%  [R0402]
R103  10K/4/5%  [R0402]
R104  22R/4/5%  [R0402]
R105  22R/4/5%  [R0402]
R106  100R/4/5%  [R0402]
R540  0R/4/5%  [R0402]
U12  RS1G32XC5  [SC70-5]
U13  RS1G32XC5  [SC70-5]
sheet PAGE15 - RS485
C113  10uF/6/16V  [C0603]
C114  10uF/6/16V  [C0603]
C115  10uF/6/16V  [C0603]
C116  100nF/4/50V  [C0402]
C117  100nF/4/50V  [C0402]
C118  10uF/6/16V  [C0603]
C119  DNP/C1206  [C1206]
C121  10uF/6/16V  [C0603]
C122  100nF/4/50V  [C0402]
C123  100nF/4/50V  [C0402]
C124  10uF/6/16V  [C0603]
R266  10K/4/5%  [R0402]
R267  4.7K/4/5%  [R0402]
R268  0R/4/5%  [R0402]
R269  0R/4/5%  [R0402]
R270  0R/4/5%  [R0402]
R271  DNP  [R0603]
R272  0R/4/5%  [R0402]
R273  10K/4/5%  [R0402]
R274  0R/4/5%  [R0402]
R275  4.7K/4/5%  [R0402]
R276  10K/4/5%  [R0402]
R277  DNP  [R1206]
R278  10K/4/5%  [R0402]
R279  4.7K/4/5%  [R0402]
R280  0R/4/5%  [R0402]
R281  0R/4/5%  [R0402]
R282  DNP  [R0603]
R283  0R/4/5%  [R0402]
R284  0R/4/5%  [R0402]
R285  0R/4/5%  [R0402]
R286  4.7K/4/5%  [R0402]
R287  10K/4/5%  [R0402]
U23  NSI83085A  [SOIC16-w]
U24  B0505S-1WR3  [Module-b0505s]
U25  NSI83085A  [SOIC16-w]
sheet PAGE16 - CAN
C100  10uF/6/16V  [C0603]
C101  100nF/4/50V  [C0402]
C102  100nF/4/50V  [C0402]
C103  10uF/6/16V  [C0603]
C104  47nF/4/50V  [C0402]
C105  10uF/6/16V  [C0603]
C106  10uF/6/16V  [C0603]
C107  DNP/C1206  [C1206]
C108  10uF/6/16V  [C0603]
C109  100nF/4/50V  [C0402]
C110  100nF/4/50V  [C0402]
C111  10uF/6/16V  [C0603]
C112  47nF/4/50V  [C0402]
D14  SMBJ12CA  [DO-214AA]
D15  SMBJ12CA  [DO-214AA]
D16  SMBJ12CA  [DO-214AA]
D17  SMBJ12CA  [DO-214AA]
D18  SMBJ12CA  [DO-214AA]
D19  SMBJ12CA  [DO-214AA]
D20  SMBJ12CA  [DO-214AA]
D21  SMBJ12CA  [DO-214AA]
J13  ULO-TB13-15RM/3.81-12P-4000A  [TP381-12pins-90-w]
L7  2.8kohm/200mA  [indcm-act45b]
L8  2.8kohm/200mA  [indcm-act45b]
R252  0R/4/5%  [R0402]
R253  0R/4/5%  [R0402]
R254  0R/4/5%  [R0402]
R255  60.4R/6/1%  [R0603]
R256  60.4R/6/1%  [R0603]
R257  0R/4/5%  [R0402]
R258  10K/4/5%  [R0402]
R259  DNP  [R1206]
R260  0R/4/5%  [R0402]
R261  0R/4/5%  [R0402]
R262  0R/4/5%  [R0402]
R263  0R/4/5%  [R0402]
R264  60.4R/6/1%  [R0603]
R265  60.4R/6/1%  [R0603]
U20  NSI1050-DDBR  [SOP8-2_54]
U21  B0505S-1WR3  [Module-b0505s]
U22  NSI1050-DDBR  [SOP8-2_54]

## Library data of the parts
C1 C2 C4 C11 C13 C18 C24 C25 C30 C35 C41 C42 C44 C45 C54 C56-C58 C60 C61 C65 C70 C71 C101 C102 C109 C110 C116 C117 C122 C123 C269 C275 = Ceramic_Capacitor: Ceramic Capacitor,100nF,50V,+/-10%,X7R,0402,Fenghua; Manufacturer: Fenghua; Manufacturer P/N: 0402B104K500NT; Myir P/N: 20401.80111; Part Type: Ceramic Capacitor; Reserve Value: 100nF; Datasheet: FENGHUA-Capacitor.pdf
C3 C9 C20 C21 C32 = Ceramic_Capacitor: Ceramic Capacitor,1uF, 25V,+/-10%,X5R,0603,Samsung; Manufacturer: Samsung; Manufacturer P/N: CL10A105KA8NNNC; Myir P/N: 20401.80063; Part Type: Ceramic Capacitor; Reserve Value: 1uF; Datasheet: Samsung.pdf
C5 C10 C12 C22 C23 C332-C338 = Ceramic_Capacitor: Ceramic Capacitor,22uF,25V,+/-10%,X5R,1206,Samsung; Manufacturer: Samsung; Manufacturer P/N: CL31A226KAHNNNE; Myir P/N: 20401.00064; Part Type: Ceramic Capacitor; Reserve Value: 22uF; Datasheet: Samsung.pdf
C6 = Aluminum_Electrolytic_Capacitor: Aluminum Electrolytic Capacitor,100uF,+/-20%,25V 100mA,6.3X7.7mm,SMD,Lelon; Manufacturer: Lelon; Manufacturer P/N: VEJ101M1ETR-0607; Myir P/N: 20404.80024; Part Type: Aluminum Electrolytic Capacitor; Reserve Value: 100uF; Datasheet: VEJ.pdf
C14 C26 C38 C263-C266 C324 = Ceramic_Capacitor: Ceramic Capacitor,10nF,50V,+/-10%,X7R,0402,Fenghua; Manufacturer: Fenghua; Manufacturer P/N: 0402B103K500NT; Myir P/N: 20401.80103; Part Type: Ceramic Capacitor; Reserve Value: 10nF; Datasheet: FENGHUA-Capacitor.pdf
C15-C17 C27-C29 C39 C323 C328 C329 C331 = Ceramic_Capacitor: Ceramic Capacitor,47uF,10V,+/-20%,X5R,1206,Samsung; Manufacturer: Samsung; Manufacturer P/N: CL31A476MPHNNNE; Myir P/N: 20401.80106; Part Type: Ceramic Capacitor; Reserve Value: 47uF; Datasheet: Samsung.pdf
C19 C31 = Ceramic_Capacitor: Ceramic Capacitor,2.2nF,50V,+/-10%,X7R,0402,Fenghua; Manufacturer: Fenghua; Manufacturer P/N: 0402B222K500NT; Myir P/N: 20401.80236; Part Type: Ceramic Capacitor; Reserve Value: 2.2nF; Datasheet: FENGHUA-Capacitor.pdf
D1 = General_Diode: Diode,TVS Single Uni-dir 15V 1500W,DO-214AB(SMC),UN; Manufacturer: UN; Myir P/N: 20701.00051; Part Type: Diode; Datasheet: UN-SMCJ.pdf
F1 = Fuse: Fuse,Resettable 4A 75V,SMD 1206,TLC; Manufacturer: TLC; Manufacturer P/N: F12F4; Myir P/N: 20801.00014; Part Type: Resettable Fuse; Reserve Value: 4A; Datasheet: F12F Series.pdf
J1 = DC-738-032XX009: Connector,DC Jack,Male,Right angle,3A,Φ2.0mm,DIP,Bluck,SongCheng; Manufacturer: SongCheng; Myir P/N: 21115.00005; Part Type: DC Connector; Datasheet: 738-032XX009.pdf
L1 = COMMON_CHOKE_1: Filters,2 Function(s), 80V, 5A,-40~85℃,L7.0XB6.0XH3.5,TDK; Manufacturer: TDK; Manufacturer P/N: ACM7060-301-2PL-TL01; Myir P/N: 20504.00009; Part Type: Common Inductor; Reserve Value: 100MHz; Datasheet: cmf_commercial_power_acm7060_zh.pdf
L2 L3 = Inductor: Power Inductor,1.0uH 20%,26mOhm 11.1A SMD 4.0*2.0*2.0mm,Sunlord; Manufacturer: Sunlord; Manufacturer P/N: WPN4020H1R0MT; Myir P/N: 20501.00037; Part Type: Power Inductor; Reserve Value: 1.0uH; Datasheet: WPN series of SMD Power Inductor1.pdf
R1 = Resister: Thick Film Resistor,10K,+/-5%,1/10W,-55°C ~ 155°C,SMD,0603,Fenghua; Manufacturer: Fenghua; Manufacturer P/N: RS-03K103JT; Myir P/N: 20301.00257; Part Type: Thick Film Resistor; Reserve Value: 10K; Datasheet: FHsheet_2018-07-30.PDF
R2 = Resister: Thick Film Resistor,10K,+/-5%,1/16W,-55°C ~ 155°C,SMD,0402,Fenghua; Manufacturer: Fenghua; Manufacturer P/N: RC-02W103JT; Myir P/N: 20301.00199; Part Type: Thick Film Resistor; Reserve Value: 10K; Datasheet: FH规格书_2018-07-30.pdf
R3 R10 R66 = Resister: Thick Film Resistor,100K,+/-5%,,1/16W,-55°C ~ 155°C,SMD,0402,Fenghua; Manufacturer: Fenghua; Manufacturer P/N: RC-02W104JT; Myir P/N: 20301.00210; Part Type: Thick Film Resistor; Reserve Value: 100K; Datasheet: FHsheet_2018-07-30.PDF
R4 R6 R15 R34-R48 R64 R65 R68-R74 R76 R77 R103 R258 R266 R273 R276 R278 R287 = Resister: Thick Film Resistor,10K,+/-5%,1/16W,-55°C ~ 155°C,SMD,0402,Fenghua; Manufacturer: Fenghua; Manufacturer P/N: RC-02W103JT; Myir P/N: 20301.00199; Part Type: Thick Film Resistor; Reserve Value: 10K; Datasheet: FHsheet_2018-07-30.PDF
R7 R13 R50 = Resister: Thick Film Resistor,1K,+/-5%,1/16W,-55°C ~ 155°C,SMD,0402,Fenghua; Manufacturer: Fenghua; Manufacturer P/N: RC-02W102JT; Myir P/N: 20301.80389; Part Type: Thick Film Resistor; Reserve Value: 1K; Datasheet: FHsheet_2018-07-30.PDF
R8 R14 = Resister: Thick Film Resistor,59K,+/-1%,1/16W,-55°C ~ 155°C,SMD,0402,Fenghua; Manufacturer: Fenghua; Manufacturer P/N: RC-02W5902FT; Myir P/N: 20301.00207; Part Type: Thick Film Resistor; Reserve Value: 59K; Datasheet: FHsheet_2018-07-30.PDF
R9 R16 = Resister: Thick Film Resistor,8.06K,+/-1%,1/16W,-55°C ~ 155°C,SMD,0402,Fenghua; Manufacturer: Fenghua; Manufacturer P/N: RC-02W8061FT; Myir P/N: 20301.00198; Part Type: Thick Film Resistor; Reserve Value: 8.06K; Datasheet: FHsheet_2018-07-30.PDF
R536 = Resister: Thick Film Resistor,0.01R,+/-1%,1/4W,-55°C ~ 155°C,SMD,1206,Fenghua; Manufacturer: Fenghua; Manufacturer P/N: RBF-06YR010FT; Myir P/N: 20301.00225; Part Type: Thick Film Resistor; Reserve Value: 0.01R; Datasheet: FHsheet_2018-07-30.PDF
SW1 = SS-12D10-L9-B: slide switch,5A current,vertical; Manufacturer: XKB; Myir P/N: 21203.00010; Part Type: Switch; Datasheet: SS-12D10-XX-X.pdf
TP1 TP2 TP7 TP9 TP10 = TP_7: DESIG: testing PAD; FAB: NA; REF: NA; VAL: NOT POPULATED
TP3 TP5 TP6 TP8 = TP: DESIG: testing PAD; FAB: NA; REF: NA; VAL: NOT POPULATED
U1 U2 = SY8388ARHC: IC,High Efficiency Fast Response,8A,24V Input Synchronous Step Down Regulator,-45~85℃,SMD,QFN2.5×2.5-16,Reel,Silergy; Manufacturer: Silergy; Myir P/N: 20103.00108; Part Type: Power Management; Datasheet: AN_SY8388A.pdf
C33 C34 C40 C43 C325 C330 = Ceramic_Capacitor: Ceramic Capacitor,22uF,10V,+/-20%,X5R,0805,Samsung; Manufacturer: Samsung; Manufacturer P/N: CL21A226MPQNNNE; Myir P/N: 20401.00087; Part Type: Ceramic Capacitor; Reserve Value: 22uF; Datasheet: Samsung.pdf
C36 C37 = Ceramic_Capacitor: Ceramic Capacitor,1nF,50V,+/-10%,X7R,0402,Fenghua; Manufacturer: Fenghua; Manufacturer P/N: 0402B102K500NT; Myir P/N: 20401.80096; Part Type: Ceramic Capacitor; Reserve Value: 1nF; Datasheet: FENGHUA-Capacitor.pdf
C46 = Ceramic_Capacitor: Ceramic Capacitor,10uF, 6.3V, +/-20%, X5R, 0402,Samsung; Manufacturer: Samsung; Manufacturer P/N: CL05A106MQ5NUNC; Myir P/N: 20401.00084; Part Type: Ceramic Capacitor; Reserve Value: 10uF; Datasheet: Samsung.pdf
C47 = Ceramic_Capacitor: Ceramic Capacitor,22uF,6.3V,+/-20%,X5R,0603,Samsung; Manufacturer: Samsung; Manufacturer P/N: CL10A226MQ8NRNC; Myir P/N: 20401.00086; Part Type: Ceramic Capacitor; Reserve Value: 22uF; Datasheet: Samsung.pdf
C320 = Ceramic_Capacitor: Ceramic Capacitor,1uF,6.3V,+/-20%,X5R,SMD,0402,Reel,Fenghua; Manufacturer: Fenghua; Manufacturer P/N: 0402X105M6R3NT; Myir P/N: 20401.00102; Part Type: Ceramic Capacitor; Reserve Value: 1uF; Datasheet: FENGHUA-Capacitor.pdf
L4 L5 = Inductor: Power Inductor,1.0uH 20%,32mOhm 5200mA SMD 2.5*2.0*1.0mm,Sunlord; Manufacturer: ATR; Manufacturer P/N: WPN252010UF1R0MT; Myir P/N: 20501.00027; Part Type: Power Inductor; Reserve Value: 1.0uH; Datasheet: WPN.pdf
R11 R573 = Resister: Thick Film Resistor,100K,+/-5%,1/16W,-55℃~155℃,SMD,0402,Fenghua; Manufacturer: Fenghua; Manufacturer P/N: RC-02W104JT; Myir P/N: 20301.00210; Part Type: Thick Film Resistor; Reserve Value: 100K; Datasheet: FHsheet_2018-07-30.PDF
R17 R49 R63 = Resister: DNP; Manufacturer: DNP; Manufacturer P/N: DNP; Myir P/N: DNP; Part Type: DNP; Reserve Value: DNP; Datasheet: DNP
R18 R23 = Resister: Thick Film Resistor,200K,+/- 1%,1/16W,-55°C ~ 155°C,SMD,0402,Fenghua; Manufacturer: Fenghua; Manufacturer P/N: RC-02W2003FT; Myir P/N: 20301.80390; Part Type: Thick Film Resistor; Reserve Value: 200K; Datasheet: FHsheet_2018-07-30.PDF
R19 R22 = Resister: Thick Film Resistor,56K,+/-1%,1/16W,-55℃~155℃,SMD,0402,Fenghua; Manufacturer: Fenghua; Manufacturer P/N: RC-02K5602FT; Myir P/N: 20301.80444; Part Type: Thick Film Resistor; Reserve Value: 56K; Datasheet: FHsheet-20230524.pdf
R20 = Resister: Thick Film Resistor,44.2K,+/-1%,1/16W,-55°C ~ 155°C,SMD,0402,Fenghua; Manufacturer: Fenghua; Manufacturer P/N: RC-02K4422FT; Myir P/N: 20301.00275; Part Type: Thick Film Resistor; Reserve Value: 44.2K; Datasheet: FHsheet_2018-07-30.PDF
R21 = Resister: Thick Film Resistor,30K,+/-1%,1/16W,-55℃~ 155℃,SMD,0402,Fenghua; Manufacturer: Fenghua; Manufacturer P/N: RC-02W3002FT; Myir P/N: 20301.00284; Part Type: Thick Film Resistor; Reserve Value: 30K; Datasheet: FHsheet_2018-07-30.PDF
R24 = Resister: Thick Film Resistor,100K,+/-1%,1/16W,-55°C~155°C,SMD,0402,Fenghua; Manufacturer: Fenghua; Manufacturer P/N: RC-02W1003FT; Myir P/N: 20301.00264; Part Type: Thick Film Resistor; Reserve Value: 100K; Datasheet: FHsheet_2018-07-30.PDF
R544 = Resister: Thick Film Resistor,100K,+/-5%,1/16W,-55℃~155℃,SMD,0402,Fenghua; Manufacturer: Fenghua; Manufacturer P/N: RC-02K104JT; Myir P/N: 20301.00210; Part Type: Thick Film Resistor; Reserve Value: 100K; Datasheet: FHsheet-20230524.pdf
U3 U4 = MP2143: IC,2.5V to 5.5V Input,3AOutput,1.2MHz,Synchronous Step Down Switcher,SMD,TSOT23-8,ACE,MPS; Manufacturer: MPS; Myir P/N: 20103.00029; Part Type: Power Management; Datasheet: MP2143.pdf
C55 = Ceramic_Capacitor: Ceramic Capacitor,2.2uF, 16V,+/-10%, X5R, 0603,Samsung; Manufacturer: Samsung; Manufacturer P/N: CL10A225KO8NNNC; Myir P/N: 20401.00081; Part Type: Ceramic Capacitor; Reserve Value: 2.2uF; Datasheet: Samsung.pdf
D2-D8 D56 D57 = TVS_Diode: Diode,TVS,5.6VDC,SMD,D0402,TDK; Manufacturer: TDK; Myir P/N: 20701.00001; Part Type: Diode; Datasheet: B72590D0050H160.pdf
FB1 FB2 = Ferrite_Bead: Ferrite Bead,220R@100Mhz,1.5A,+/-25%,SMD,0603,Fenghua; Manufacturer: Fenghua; Manufacturer P/N: CBM160808U221T; Myir P/N: 20601.80007; Part Type: Ferrite Bead; Reserve Value: 220R; Datasheet: CBM160808U221T.pdf
J2 = TF-CARD: Connector,MicroSD Card,Gold Flash,Nature,SMD,ATOM; Manufacturer: ATOM; Myir P/N: 21112.00002; Part Type: Other Connector; Datasheet: MR01A-01211.pdf
C59 = Ceramic_Capacitor: Ceramic Capacitor,4.7uF,6.3V,+/-20%,X5R,0402,Samsung; Manufacturer: Samsung; Manufacturer P/N: CL05A475MQ5NRNC; Myir P/N: 20401.80098; Part Type: Ceramic Capacitor; Reserve Value: 4.7uF; Datasheet: Samsung.pdf
R51-R61 R78-R85 R92 R252-R254 R257 R260-R263 R268-R270 R272 R274 R280 R281 R283-R285 R502 R504 R540 = Resister: Thick Film Resistor,0R,+/-5%,1/16W,-55°C ~ 155°C,SMD,0402,Fenghua; Manufacturer: Fenghua; Manufacturer P/N: RC-02000JT; Myir P/N: 20301.00186; Part Type: Thick Film Resistor; Reserve Value: 0R; Datasheet: FHsheet_2018-07-30.PDF
R62 R104 R105 = Resister: Thick Film Resistor,22R,+/-5%,1/16W,-55°C ~ 155°C,SMD,0402,Fenghua; Manufacturer: Fenghua; Manufacturer P/N: RC-02W220JT; Myir P/N: 20301.00187; Part Type: Thick Film Resistor; Reserve Value: 22R; Datasheet: FHsheet_2018-07-30.PDF
U8 = 74LVC1G08GW: IC,Single 2-Input Positive-AND Gate,SMD,SOT23-5,Runic; Manufacturer: Runic; Myir P/N: 20105.00034; Part Type: Logic; Datasheet: RS1G08XF5.pdf
U55 = Flash-S28HS512TGABHV010: IC,512Mb,QSPI Nor Flash,6x8mm package,-40℃~+85℃, Industrial Plus,Tray,Infineon; Manufacturer: Infineon; Myir P/N: 20102.00112; Part Type: Memory; Datasheet: INFN-S-A0014638083-1.pdf
C62 C100 C103 C105 C106 C108 C111 C113-C115 C118 C121 C124 C270 C273 C274 = Ceramic_Capacitor: Ceramic Capacitor,10uF,16V,+/-20%,X5R,0603,Samsung; Manufacturer: Samsung; Manufacturer P/N: CL10A106MO8NQNC; Myir P/N: 20401.80062; Part Type: Ceramic Capacitor; Reserve Value: 10uF; Datasheet: Samsung.pdf
C271 = Ceramic_Capacitor: Ceramic Capacitor,100nF,16V,+/-10%,X7R,0402,Fenghua; Manufacturer: Fenghua; Manufacturer P/N: 0402B104K160NT; Myir P/N: 20401.80188; Part Type: Ceramic Capacitor; Reserve Value: 100nF; Datasheet: FENGHUA-Capacitor.pdf
C272 = CERAMIC_CAPACITOR: Ceramic Capacitor, 10pF,+/-5%,C0G,50V,SMD,0402; Manufacturer: Murata; Manufacturer P/N: GRM1555C1H100JA01D; Myir P/N: 2040100002; Part Type: Ceramic Capacitor; Reserve Value: 10pF; Datasheet: Ceramic Capacitor.pdf
J27 J28 = ANT4-0403: Connector,UMCC RCP 0Hz to 6GHz 50Ohm Solder ST SMD Gold Over Nickel,FLY_Core; Manufacturer: FLY_Core; Myir P/N: 21114.00004; Part Type: Antenna Connector; RP1 Manufacturer P/N: 1566230-1; RP1 Myir P/N: 21114.00001; Datasheet: ANB02001-125.pdf
L13 = INDUCTOR: Power Inductor,2.2uH,+/-20,SPH,3.0*3.0*1.2mm,SMD,Sunlord; Manufacturer: Sunlord; Manufacturer P/N: SPH3012H2R2MT; Myir P/N: 20501.00034; Part Type: Power Inductor; Datasheet: SPH series of SMD Power Inductor.pdf
R94 R267 R275 R279 R286 R511 = Resister: Thick Film Resistor,4.7K,+/-5%,1/16W,-55°C ~ 155°C,SMD,0402,Fenghua; Manufacturer: Fenghua; Manufacturer P/N: RC-02W472JT; Myir P/N: 20301.80393; Part Type: Thick Film Resistor; Reserve Value: 4.7K; Datasheet: FHsheet_2018-07-30.PDF
R512 = Resister: Thick Film Resistor,22R,+/-5%,1/16W,-55°C ~ 155°C,SMD,0402,Fenghua; Manufacturer: Fenghua; Manufacturer P/N: RC-02W220JT; Myir P/N: 20301.00187; Part Type: Thick Film Resistor; Reserve Value: 22R; Datasheet: FH规格书_2018-07-30.pdf
R513 = RESISTER: Thick Film Resistor,1K,+/-1%,1/16W,SMD,0402,Yageo; Manufacturer: Yageo; Manufacturer P/N: RC0402FR-071KL; Myir P/N: 2030100021; Part Type: Thick Film Resistor; Reserve Value: 1K; Datasheet: 0402_Thick Film Resistor.pdf
U47 = FGL297BSRX-00: WIFI/Bluetooth module,WiFi Dual-band 2X2 11ac,Bluetooth V5.0,-30℃~85℃,Size 15*13*2.3mm,SMD,Fn-Link; Manufacturer: Fn-link; Myir P/N: 20205.80004; Part Type: WIFI Module; Datasheet: Fn-Link_L297B-SR_datasheet_V1.2_20220215.pdf
Y6 = Oscillator_4P: Oscillator,32.768KHz,+/-30ppm,15pF,3.3V,4Pin,3225,-40℃to+85℃,SMD,SJK; Manufacturer: SJK; Manufacturer P/N: SJK-3N32768K3C0430B8; Myir P/N: 20902.00010; Part Type: Oscillator; RP1 Manufacturer P/N: HSO321S-32.768KHz; RP1 Myir P/N: 20902.00002; Reserve Value: 32.768kHZ; Datasheet: 3N32768K3C0430B8.pdf
C72 = Ceramic_Capacitor: Ceramic Capacitor,10pF,50V,+/-5%,C0G,0402,Fenghua; Manufacturer: Fenghua; Manufacturer P/N: 0402CG100J500NT; Myir P/N: 20401.00076; Part Type: Ceramic Capacitor; Reserve Value: 10pF; Datasheet: FENGHUA-Capacitor.pdf
J4 = 2X10PIN: Connector,Pin Header,Straight,Male,2x10Pin,1.27mm pitch,8.7,3.0,Gold Flash 1u, black,SMD,WCON; Manufacturer: Wcon; Myir P/N: 21101.80026; Part Type: Connector; Datasheet: 1325-1210G0M087CR01.pdf
R106 = Resister: Thick Film Resistor,100R,+/-5%,1/16W,-55°C ~ 155°C,SMD,0402,Fenghua; Manufacturer: Fenghua; Manufacturer P/N: RC-02W101JT; Myir P/N: 20301.00191; Part Type: Thick Film Resistor; Reserve Value: 100R; Datasheet: FHsheet_2018-07-30.PDF
U12 U13 = RS1G32XC5: IC,Single 2-Input Positive-OR Gate,SMD,SC70-5(SOT353),RUNIC; Manufacturer: Runic; Myir P/N: 20105.00039; Part Type: Logic; Datasheet: RS1G32_(RevA.3).pdf
C107 C119 = Ceramic_Capacitor: DNP; Manufacturer: DNP; Manufacturer P/N: DNP; Myir P/N: DNP; Part Type: DNP; Reserve Value: DNP; Datasheet: DNP
R271 R282 = RESISTER: Thick Film Resistor,1K,+/-5%,1/10W,-55°C ~ 155°C,SMD,0603,Fenghua; Manufacturer: Fenghua; Manufacturer P/N: RS-03K102JT; Myir P/N: 20301.00218; Part Type: Thick Film Resistor; Reserve Value: 1K; Datasheet: FH规格书_2018-07-30.pdf
R259 R277 = Resister: Thick Film Resistor,1M,+/-5%,1/4W,-55°C ~ 155°C,SMD,1206,Fenghua; Manufacturer: Fenghua; Manufacturer P/N: RS-06K105JT; Myir P/N: 20301.00226; Part Type: Thick Film Resistor; Reserve Value: 1M; Datasheet: FH规格书_2018-07-30.pdf
U23 U25 = ISO3082DW: IC,High Reliability Isolat-ed Half and Full-Duplex RS-485 Transceiver,SMD,SOIC16,Novosense; Manufacturer: Novosense; Myir P/N: 20107.00067; Part Type: Interface; RP1 Myir P/N: 20107.00018; Datasheet: NSI83085A.pdf
U21 U24 = B0505S-1W: Power Supply Module,input 5V,output 5.5V,1W,Size 11.6*6*10.16mm,-40-105℃,SIP-4,Mornsun; Manufacturer: Mornsun; Myir P/N: 20204.00016; Part Type: Power Module; Datasheet: B0505S-1WR3.pdf
C104 C112 = Ceramic_Capacitor: Ceramic Capacitor,47nF,50V,+/-10%,C0G,0402,Fenghua; Manufacturer: Fenghua; Manufacturer P/N: 0402B473K500NT; Myir P/N: 20401.80241; Part Type: Ceramic Capacitor; Reserve Value: 47nF; Datasheet: FENGHUA-Capacitor.pdf
D14-D21 = TVS_Diode: Diode,TVS Bi-Dir 12V 600W, DO-214AA(SMB); Manufacturer: UN; Myir P/N: 20701.00027; Part Type: Diode; Datasheet: UN-SMBJ.pdf
J13 = 1x12PIN: Connector,Male Right Angle,Pluggable Terminal Block,12Pin,3.81mm Pitch,Green,ULO; Manufacturer: ULO; Myir P/N: 21109.00036; Part Type: Connector; Datasheet: ULO-TB13-15RM_3.81-XXP-Y000A.pdf
L7 L8 = COMMON_CHOKE_1: Inductor,Common Choke,2.8kohm@100MHz,±25%,200mA,SMD 4.5*3.2*2.8mm; Manufacturer: TDK; Manufacturer P/N: ACT45B-510-2P-TL003; Myir P/N: 20504.00003; Part Type: Common Inductor; Reserve Value: 2.8kohm; Datasheet: ACT45B.pdf
R255 R256 R264 R265 = Resister: Thick Film Resistor,60.4R,+/-1%,1/10W,-55°C ~ 155°C,SMD,0603,Fenghua; Manufacturer: Fenghua; Manufacturer P/N: RS-03K60R4FT; Myir P/N: 20301.00255; Part Type: Thick Film Resistor; Reserve Value: 60.4R; Datasheet: FHsheet_2018-07-30.PDF
U20 U22 = NSI1050-DDBR: IC,isolated CAN Transceiver,SMD,SOP8,NSI1050,Novosense; Manufacturer: Novosense; Myir P/N: 20107.00065; Part Type: Interface; RP1 Manufacturer P/N: ISO1050DUBR; RP1 Myir P/N: 20107.00023; RP2 Manufacturer P/N: CA-IS3050U; RP2 Myir P/N: 20107.00081; Datasheet: NSI1050.pdf

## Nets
GND: C1.2 C2.2 C3.2 C4.2 C5.2 C6.2(N) C9.2 C10.2 C12.2 C13.2 C14.2 C15.2 C16.2 C17.2 C18.2 C20.2 C21.2 C22.2 C23.2 C24.2 C26.2 C27.2 C28.2 C29.2 C30.2 C32.2 C33.2 C34.2 C35.2 C38.2 C39.2 C40.2 C41.2 C42.2 C43.2 C44.2 C45.2 C46.2 C47.2 C54.2 C55.2 C56.2 C57.2 C58.2 C59.2 C60.2 C61.2 C62.2 C65.2 C70.2 C71.2 C72.2 C100.2 C101.2 C105.2 C107.1 C108.2 C109.2 C113.2 C115.2 C116.2 C119.1 C121.2 C122.2 C263.2 C264.2 C265.2 C266.2 C269.2 C270.2 C271.2 C272.2 C273.2 C274.2 C275.2 C320.2 C323.2 C324.2 C325.2 C328.2 C329.2 C330.2 C331.2 C332.2 C333.2 C334.2 C335.2 C336.2 C337.2 C338.2 D2.1 D3.1 D4.1 D5.1 D6.1 D7.1 D8.1 D56.1 D57.1 J2.6(VSS) J2.10(GND) J2.11(Sh1) J2.12(Sh2) J2.13(Sh3) J4.10 J4.12 J4.16 J4.20 J27.3(GND1) J27.4(GND2) J28.3(GND1) J28.4(GND2) L1.3 R1.2 R2.2 R6.2 R9.2 R15.2 R16.2 R19.2 R20.2 R22.2 R24.2 R50.1 R66.2 R92.2 R259.1 R276.2 R277.1 R287.2 R513.2 TP1.1(TP) U1.6(GND) U1.14(GND) U1.17(PGND) U2.6(GND) U2.14(GND) U2.17(PGND) U3.4(PGND) U3.6(AGND) U4.4(PGND) U4.6(AGND) U8.3(GND) U12.3(GND) U13.3(GND) U20.4(GND1) U21.1(GND) U22.4(GND1) U23.2(GND1) U23.7(GND1) U23.8(GND1) U24.1(GND) U25.2(GND1) U25.7(GND1) U25.8(GND1) U47.1(GND) U47.3(GND) U47.4(GND) U47.5(GND) U47.6(GND) U47.7(GND) U47.8(GND) U47.10(GND) U47.11(GND) U47.23(GND) U47.32(GND) U47.39(GND) U55.B3(Vss) U55.C1(VSSQ) U55.E5(VSSQ) Y6.2(GND) ; also on sheet 12 13 14 15 16 17 18 19 20 21 22 23 24 25
GND_EARTH: J1.5 J1.6 ; also on sheet 14 17 18 19 23 25
VDD_1V8: C36.1 C45.1 C46.1 C47.1 C56.1 C57.1 C58.1 C59.1 C60.1 C323.1 C324.1 C331.1 L5.2 R23.1 R41.1 R42.1 R43.1 R44.1 R45.1 R46.1 R47.1 R48.1 R49.1 R64.1 R65.1 R68.1 TP10.1(TP) U4.5(OUT) U8.5(VCC) U55.B4(Vcc) U55.D1(VCCQ) U55.E4(VCCQ) ; also on sheet 13 16
VDD_1V8_FB: C36.2 R23.2 R24.1 U4.7(FB)
VDD_1V8_SW: L5.1 U4.3(SW)
VDD_3V3: C37.1 C38.1 C39.1 C40.1 C41.1 C42.1 C65.1 C70.1 C71.1 C100.1 C101.1 C108.1 C109.1 C115.1 C116.1 C121.1 C122.1 FB1.1 FB2.2 J4.5 L4.2 R18.1 R94.1 R103.1 R266.1 R278.1 R544.1 TP9.1(TP) U3.5(OUT) U12.5(VCC) U13.5(VCC) U20.1(VDD1) U22.1(VDD1) U23.1(VDD1) U25.1(VDD1) ; also on sheet 12 13 14 16 17 18 19 20 21 25
VDD_3V3_SW: L4.1 U3.3(SW)
VDD_5V: C26.1 C27.1 C28.1 C29.1 C30.1 C33.1 C34.1 C35.1 C43.1 C44.1 C105.1 C113.1 C325.1 C328.1 C329.1 C330.1 L3.2 R10.1 R13.1 R14.1 R17.1 R21.1 TP7.1(TP) U3.2(VIN) U4.2(VIN) U21.2(VIN) U24.2(VIN) ; also on sheet 12 13 14 17 24
VDD_5V_SW: C25.2 L3.1 U2.5(LX1) U2.15(LX2) U2.16(LX3)
VDD_12V: C10.1 C12.1 C13.1 C22.1 C23.1 C24.1 C334.1 C335.1 C336.1 C337.1 R1.1 R2.1 R4.1 R11.1 SW1.3 U1.2(IN1) U1.3(IN2) U1.4(IN3) U2.2(IN1) U2.3(IN2) U2.4(IN3) ; also on sheet 12
VDD_12VSW: C1.1 C2.1 C3.1 C4.1 C5.1 C6.1(P) C332.1 C333.1 C338.1 L1.4 SW1.2 TP2.1(TP)
VDD_485_5V: C114.1 C117.1 C118.1 C123.1 C124.1 R267.1 R273.1 R279.1 U23.16(VDD2) U24.4(+VO) U25.16(VDD2)
VDD_BLE_3V3: C61.1 C62.1 C269.1 C270.1 C271.1 FB2.1 R69.1 R70.1 R71.1 R72.1 R73.1 R74.1 R76.1 R77.1 R511.1 U47.34(VDDIO) U47.36(VBAT) Y6.4(VCC/Vdd)
VDD_CAN_5V: C102.1 C103.1 C106.1 C110.1 C111.1 R258.1 U20.8(VDD2) U21.4(+VO) U22.8(VDD2)
VDD_IN: F1.1 J1.4
VDD_IN_GND: D1.1 J1.2 L1.2
VDD_MMC1_SD: C54.1 C55.1 FB1.2 J2.4(VCC) R34.1 R35.1 R36.1 R37.1 R38.1 R39.1 R40.1
VDD_SOM_3V3: R573.1 ; also on sheet 15 22
VDD_SOM_5V: R3.1 R536.1 ; also on sheet 22
VDD_SOM_5V_R: C14.1 C15.1 C16.1 C17.1 C18.1 L2.2 R7.1 R8.1 R536.2
VDD_SOM_5V_SW: C11.2 L2.1 U1.5(LX1) U1.15(LX2) U1.16(LX3)
32.7K_CLK: C272.1 R512.2 R513.1 U47.31(LPO)
BT_RST: R73.2 U47.49(HOST_WAKE_BT) ; also on sheet 21
CANH1: D20.2 J13.2 R253.2
CANH2: D18.2 J13.5 R261.2
CANL1: D21.2 J13.1 R254.2
CANL2: D19.2 J13.4 R262.2
DS: R49.2 R50.2 R62.1 U55.C3(DS)
EN_VDD_3V3: C320.1 R17.2 R19.1 R573.2 U3.8(EN)
ISO_485: C114.2 C117.2 C118.2 C119.2 C123.2 C124.2 D14.1 D15.1 D16.1 D17.1 J13.7 J13.10 R273.2 R275.2 R277.2 R286.2 U23.9(GND2) U23.10(GND2) U23.15(GND2) U24.3(0V) U25.9(GND2) U25.10(GND2) U25.15(GND2)
ISO_CAN: C102.2 C103.2 C104.2 C106.2 C107.2 C110.2 C111.2 C112.2 D18.1 D19.1 D20.1 D21.1 J13.3 J13.6 R258.2 R259.2 U20.5(GND2) U21.3(0V) U22.5(GND2)
JTAG_cTI_RTCK: J4.9 R105.2
JTAG_cTI_TCK: J4.11 R103.2 R106.1 U12.1(A) U13.1(A)
JTAG_EMU_RSTn: R540.1 ; also on sheet 22
JTAG_EMU_RSTn_R: J4.15 R94.2 R540.2
JTAG_TDIS: J4.4 R92.1
OSPI_CLK: R51.1 R66.1 U55.B2(CK)
OSPI_CS: R54.1 R65.2 U55.C2(~{CS})
OSPI_DQ0: R41.2 R52.1 U55.D3(DQ0)
OSPI_DQ1: R42.2 R53.1 U55.D2(DQ1)
OSPI_DQ2: R43.2 R55.1 U55.C4(DQ2)
OSPI_DQ3: R44.2 R56.1 U55.D4(DQ3)
OSPI_DQ4: R45.2 R58.1 U55.D5(DQ4)
OSPI_DQ5: R46.2 R59.1 U55.E3(DQ5)
OSPI_DQ6: R47.2 R60.1 U55.E2(DQ6)
OSPI_DQ7: R48.2 R61.1 U55.E1(DQ7)
OSPI_INTn: R57.1 R64.2 U55.A5(~{INT})
OSPI_RSTn: R68.2 U8.4(Y) U55.A4(~{RESET})
PG_VDD_3V3: R21.2 R22.1 R544.2 U3.1(PG) U4.8(EN)
RS485_A1: D17.2 J13.8 R270.2 R271.1
RS485_A2: D15.2 J13.11 R281.2 R282.1
RS485_B1: D16.2 J13.9 R271.2 R272.2
RS485_B2: D14.2 J13.12 R282.2 R284.2
SEL_XDS110_INV: J4.8 U12.2(B) U13.2(B)
SoC_GPMC0_WAIT1: R269.1 ; also on sheet 22
SoC_GPMC0_WPn: R268.1 ; also on sheet 22
SoC_JTAG_EMU0: J4.13 ; also on sheet 22
SoC_JTAG_EMU1: J4.14 ; also on sheet 22
SoC_JTAG_TCK: R104.2 ; also on sheet 22
SoC_JTAG_TDI: J4.3 ; also on sheet 22
SoC_JTAG_TDO: J4.7 ; also on sheet 22
SoC_JTAG_TMS: J4.1 ; also on sheet 22
SoC_JTAG_TRSTn: J4.2 ; also on sheet 22
SoC_MCU_MCAN0_RX: R257.1 ; also on sheet 22
SoC_MCU_MCAN0_TX: R252.1 ; also on sheet 22
SoC_MCU_MCAN1_TX: R77.2 U47.15(WL_REG_ON) ; also on sheet 22
SoC_MMC1_CLK: D5.2 J2.5(CLK) R37.2 ; also on sheet 22
SoC_MMC1_CMD: D4.2 J2.3(CMD) R36.2 ; also on sheet 22
SoC_MMC1_DAT0: D6.2 J2.7(DAT0) R38.2 ; also on sheet 22
SoC_MMC1_DAT1: D7.2 J2.8(DAT1) R39.2 ; also on sheet 22
SoC_MMC1_DAT2: D2.2 J2.1(DAT2) R34.2 ; also on sheet 22
SoC_MMC1_DAT3: D3.2 J2.2(DAT3) R35.2 ; also on sheet 22
SoC_MMC1_SDCD: D8.2 J2.9(CD) R40.2 ; also on sheet 22
SoC_MMC2_CLK: R85.1 ; also on sheet 22
SoC_MMC2_CMD: R84.1 ; also on sheet 22
SoC_MMC2_DAT0: R78.1 ; also on sheet 22
SoC_MMC2_DAT1: R80.1 ; also on sheet 22
SoC_MMC2_DAT2: R82.1 ; also on sheet 22
SoC_MMC2_DAT3: R83.1 ; also on sheet 22
SoC_OSPI0_CLK: R51.2 ; also on sheet 22
SoC_OSPI0_CSn0: R54.2 ; also on sheet 22
SoC_OSPI0_CSn1: R285.1 ; also on sheet 22
SoC_OSPI0_DQ0: R52.2 ; also on sheet 22
SoC_OSPI0_DQ1: R53.2 ; also on sheet 22
SoC_OSPI0_DQ2: R55.2 ; also on sheet 22
SoC_OSPI0_DQ3: R56.2 ; also on sheet 22
SoC_OSPI0_DQ4: R58.2 ; also on sheet 22
SoC_OSPI0_DQ5: R59.2 ; also on sheet 22
SoC_OSPI0_DQ6: R60.2 ; also on sheet 22
SoC_OSPI0_DQ7: R61.2 ; also on sheet 22
SoC_OSPI0_DQS: R62.2 R63.1 ; also on sheet 22
SoC_OSPI0_ECC_FAIL: R57.2 ; also on sheet 22
SoC_OSPI0_LBCLK: R63.2 ; also on sheet 22
SoC_OSPI0_RESETOUT1: U8.1(B) ; also on sheet 22
SoC_RESETSTATz: U8.2(A) ; also on sheet 22
SoC_UART1_CTSn: U47.42(UART_RTS) ; also on sheet 22
SoC_UART1_DTRn: R260.1 ; also on sheet 22
SoC_UART1_RIn: R263.1 ; also on sheet 22
SoC_UART1_RTSn: U47.43(UART_CTS) ; also on sheet 22
SoC_UART1_RXD: R81.1 ; also on sheet 22
SoC_UART1_TXD: R79.1 ; also on sheet 22
SoC_UART4_RXD: R283.1 ; also on sheet 22
SoC_UART4_TXD: R280.1 ; also on sheet 22
SoC_USB1_DRVVBUS: R274.1 ; also on sheet 22
WIFI_2V2: C273.1 C274.1 C275.1 L13.1 U47.26(2.2VIN)
N21683802: R266.2 R269.2 U23.3((R)RXD)
N21683845: R267.2 R270.1 U23.12(A)
N21683857: R268.2 U23.6((D)TXD)
N21683901: R272.1 R275.1 U23.13(B)
N21683929: R274.2 R276.1 U23.4(~{RE}\) U23.5(DE)
N21684314: R278.2 R283.2 U25.3((R)RXD)
N21684387: R280.2 U25.6((D)TXD)
N21684482: R285.2 R287.1 U25.4(~{RE}\) U25.5(DE)
N21714485: R279.2 R281.1 U25.12(A)
N21714524: R284.1 R286.1 U25.13(B)
N21884472: D1.2 F1.2 L1.1
N21885565: R3.2 U1.7(PG)
N21885584: C11.1 U1.1(BS)
N21885634: R4.2 R6.1 U1.9(EN)
N21885693: TP3.1(TP) U1.8(MODE)
N21885737: C19.1 R7.2
N21885739: C19.2 R8.2 R9.1 U1.11(FB)
N21885780: TP5.1(TP) U1.10(ILMT)
N21885830: C20.1 U1.12(BYP)
N21893632: C9.1 U1.13(VCC)
N21900346: C37.2 R18.2 R20.1 U3.7(FB)
N22387016: C21.1 U2.13(VCC)
N22387130: R10.2 U2.7(PG)
N22387188: C25.1 U2.1(BS)
N22387215: R11.2 R15.1 U2.9(EN)
N22387217: TP6.1(TP) U2.8(MODE)
N22387362: TP8.1(TP) U2.10(ILMT)
N22387364: C31.2 R14.2 R16.1 U2.11(FB)
N22387368: C31.1 R13.2
N22387403: C32.1 U2.12(BYP)
N22483474: R104.1 U12.4(Y)
N22483498: C72.1 R106.2
N22483568: R105.1 U13.4(Y)
N22683837: C263.1 R502.2 U47.2(RF0)
N22683839: C264.1 D56.2 J27.2(IN) R502.1
N22683943: R81.2 U47.40(UART_TX)
N22683961: R79.2 U47.41(UART_RX)
N22683997: C265.1 R504.2 U47.9(RF1)
N22684003: C266.1 D57.2 J28.2(IN) R504.1
N22684239: R511.2 Y6.1(EN/Vcont/NC)
N22684315: R512.1 Y6.3(OUT/Output)
N22684386: L13.2 U47.25(LX_OUT)
N22685134: R69.2 R85.2 U47.18(SD_CLK)
N22685150: R70.2 R84.2 U47.17(SD_CMD)
N22685166: R71.2 R83.2 U47.19(SD_D3)
N22685182: R72.2 R82.2 U47.20(SD_D2)
N22685198: R74.2 R80.2 U47.22(SD_D1)
N22685204: R76.2 R78.2 U47.21(SD_D0)
N22767924: R252.2 U20.3(TXD)
N22767926: L7.1 U20.7(CANH)
N22767928: L7.4 R253.1 R255.1
N22767957: L7.3 R254.1 R256.1
N22767970: R257.2 U20.2(RXD)
N22767972: L7.2 U20.6(CANL)
N22768026: C104.1 R255.2 R256.2
N22768266: R260.2 U22.3(TXD)
N22768268: L8.1 U22.7(CANH)
N22768270: L8.4 R261.1 R264.1
N22768305: L8.3 R262.1 R265.1
N22768318: R263.2 U22.2(RXD)
N22768320: L8.2 U22.6(CANL)
N22768352: C112.1 R264.2 R265.2

Not connected (* = marked no-connect by the designer): J1 3; J4 6 17 18 19; J27 1(NC); J28 1(NC); SW1 1; U4 1(PG)*; U23 11(NC1) 14(NC2); U25 11(NC1) 14(NC2); U47 12(NC1) 13(NC2) 14(NC3) 16(WL_WAKE_HOST)* 24(NC4) 27(PCM_SYNC) 28(PCM_IN) 29(PCM_OUT) 30(PCM_CLK) 33(NC) 35(NC5) 37(NC6) 38(NC7) 44(NC8) 45(NC9) 46(NC10) 47(NC) 48(NC11) 50(BT_WAKE_HOST)*; U55 A2(DNU1) A3(DNU2) B1(DFU3) B5(DFU4) C5(DNU5)

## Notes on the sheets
sheet 1
- MCAN
- SUMMART
- MCAN0_TX
- MCAN0_RX
sheet 2
- RS-485
- SoC_UART6_TXD
- SoC_UART6_RXD
- SoC_GPIO1_51
- UART4
- SoC_GPIO0_12
- SUMMART
sheet 3
- Revision History
- Description
- Version
- Date
- By
- Ver 01
- Initial  Release.
- 2022-09-02
- Toby
- Schematic
- Sheet NO.
- Sheet Name
- 01
- REVISION  HISTORY
- 02
- SYS BLOCK DIAGRAM
- 03
- POWER BLOCK DIAGRAM
- 04
- MAIN & SOM POWER
- 05
- CARRIER BD POWER
- 06
- SD CARD INTERFACE
- 07
- OSPI FLASH INTERFACE
- 08
- WIFI & BLE
- 09
- JTAG BUFFER & CONN
- 10
- DUAL CHANNELS LVDS
- 11
- CSI - RX
- 12
- HDMI & 8 BIT GPMC
- 13
- BOOT MODE SWITCHES
- 14
- USB2.0-UART DEBUG I/F
- 15
- RS485
- 16
- MCAN
- 17
- AUDIO CODEC
- 18
- USB2.0 HUB
- 19
- M2 4G/5G MODULE
- 20
- RGMII_1 ETHERNET PHY
- 21
- RGMII_2 ETHERNET PHY
- 22
- KEY & RTC
- 23
- IO EXPANDER
- 24
- SOM INTERFACE
- 25
- ACCESSORIES
sheet 6
- 12V, 3.0AMPS POWER SUPPLY
- 5.0V, 3.0AMPS SOM POWER SUPPLY
- 4.99V
- Imax=5A,
- FB=0.6V
sheet 7
- 5.0V, 3.0AMPS SUPPLY
- Imax=3A,
- 4.99V
- Vout=[(Ru/Rd)+1]*0.6V
      =[(59/8.06)+1]*0.6V
      =4.99V
- FB=0.6V
- 3.3V, 3.0AMPS SUPPLY
- FB=0.6V
- Vout=[(Ru/Rd)+1]*0.6V
      =[(200/44.2)+1]*0.6V
      =3.3V
- 1.8V, 3AMPS SUPPLY
- Vout=[(Ru/Rd)+1]*0.6V
      =[(200/100)+1]*0.6V
      =1.8V
sheet 8
- SD CARD I/F
sheet 9
- OSPI Flash
- NOTE:
  For QSPI Configuration
  Remove 0E resistors from the following
  1.OSPI_DQ4 to OSPI_DQ7 nets (RA4)
  2.OSPI_INTn (R321)
  OSPI NOR Flash can be replaced with the Footprint
  compatible OCTAL NAND Flash (Mfr Part# W35N01JWTBAG)
- Place R63 close to the
  Memory to avoid stub
- OSPI Flash Reset
sheet 10
- Wi-Fi & Bluetooth
- Host device to wake up Bluetooth
- Full Power-Down
- MCU_GPIO0_15
sheet 11
- JTAG CONNECTOR
